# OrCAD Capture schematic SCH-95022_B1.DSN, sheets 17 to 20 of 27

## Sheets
17 Page20 HDMI Display: size C
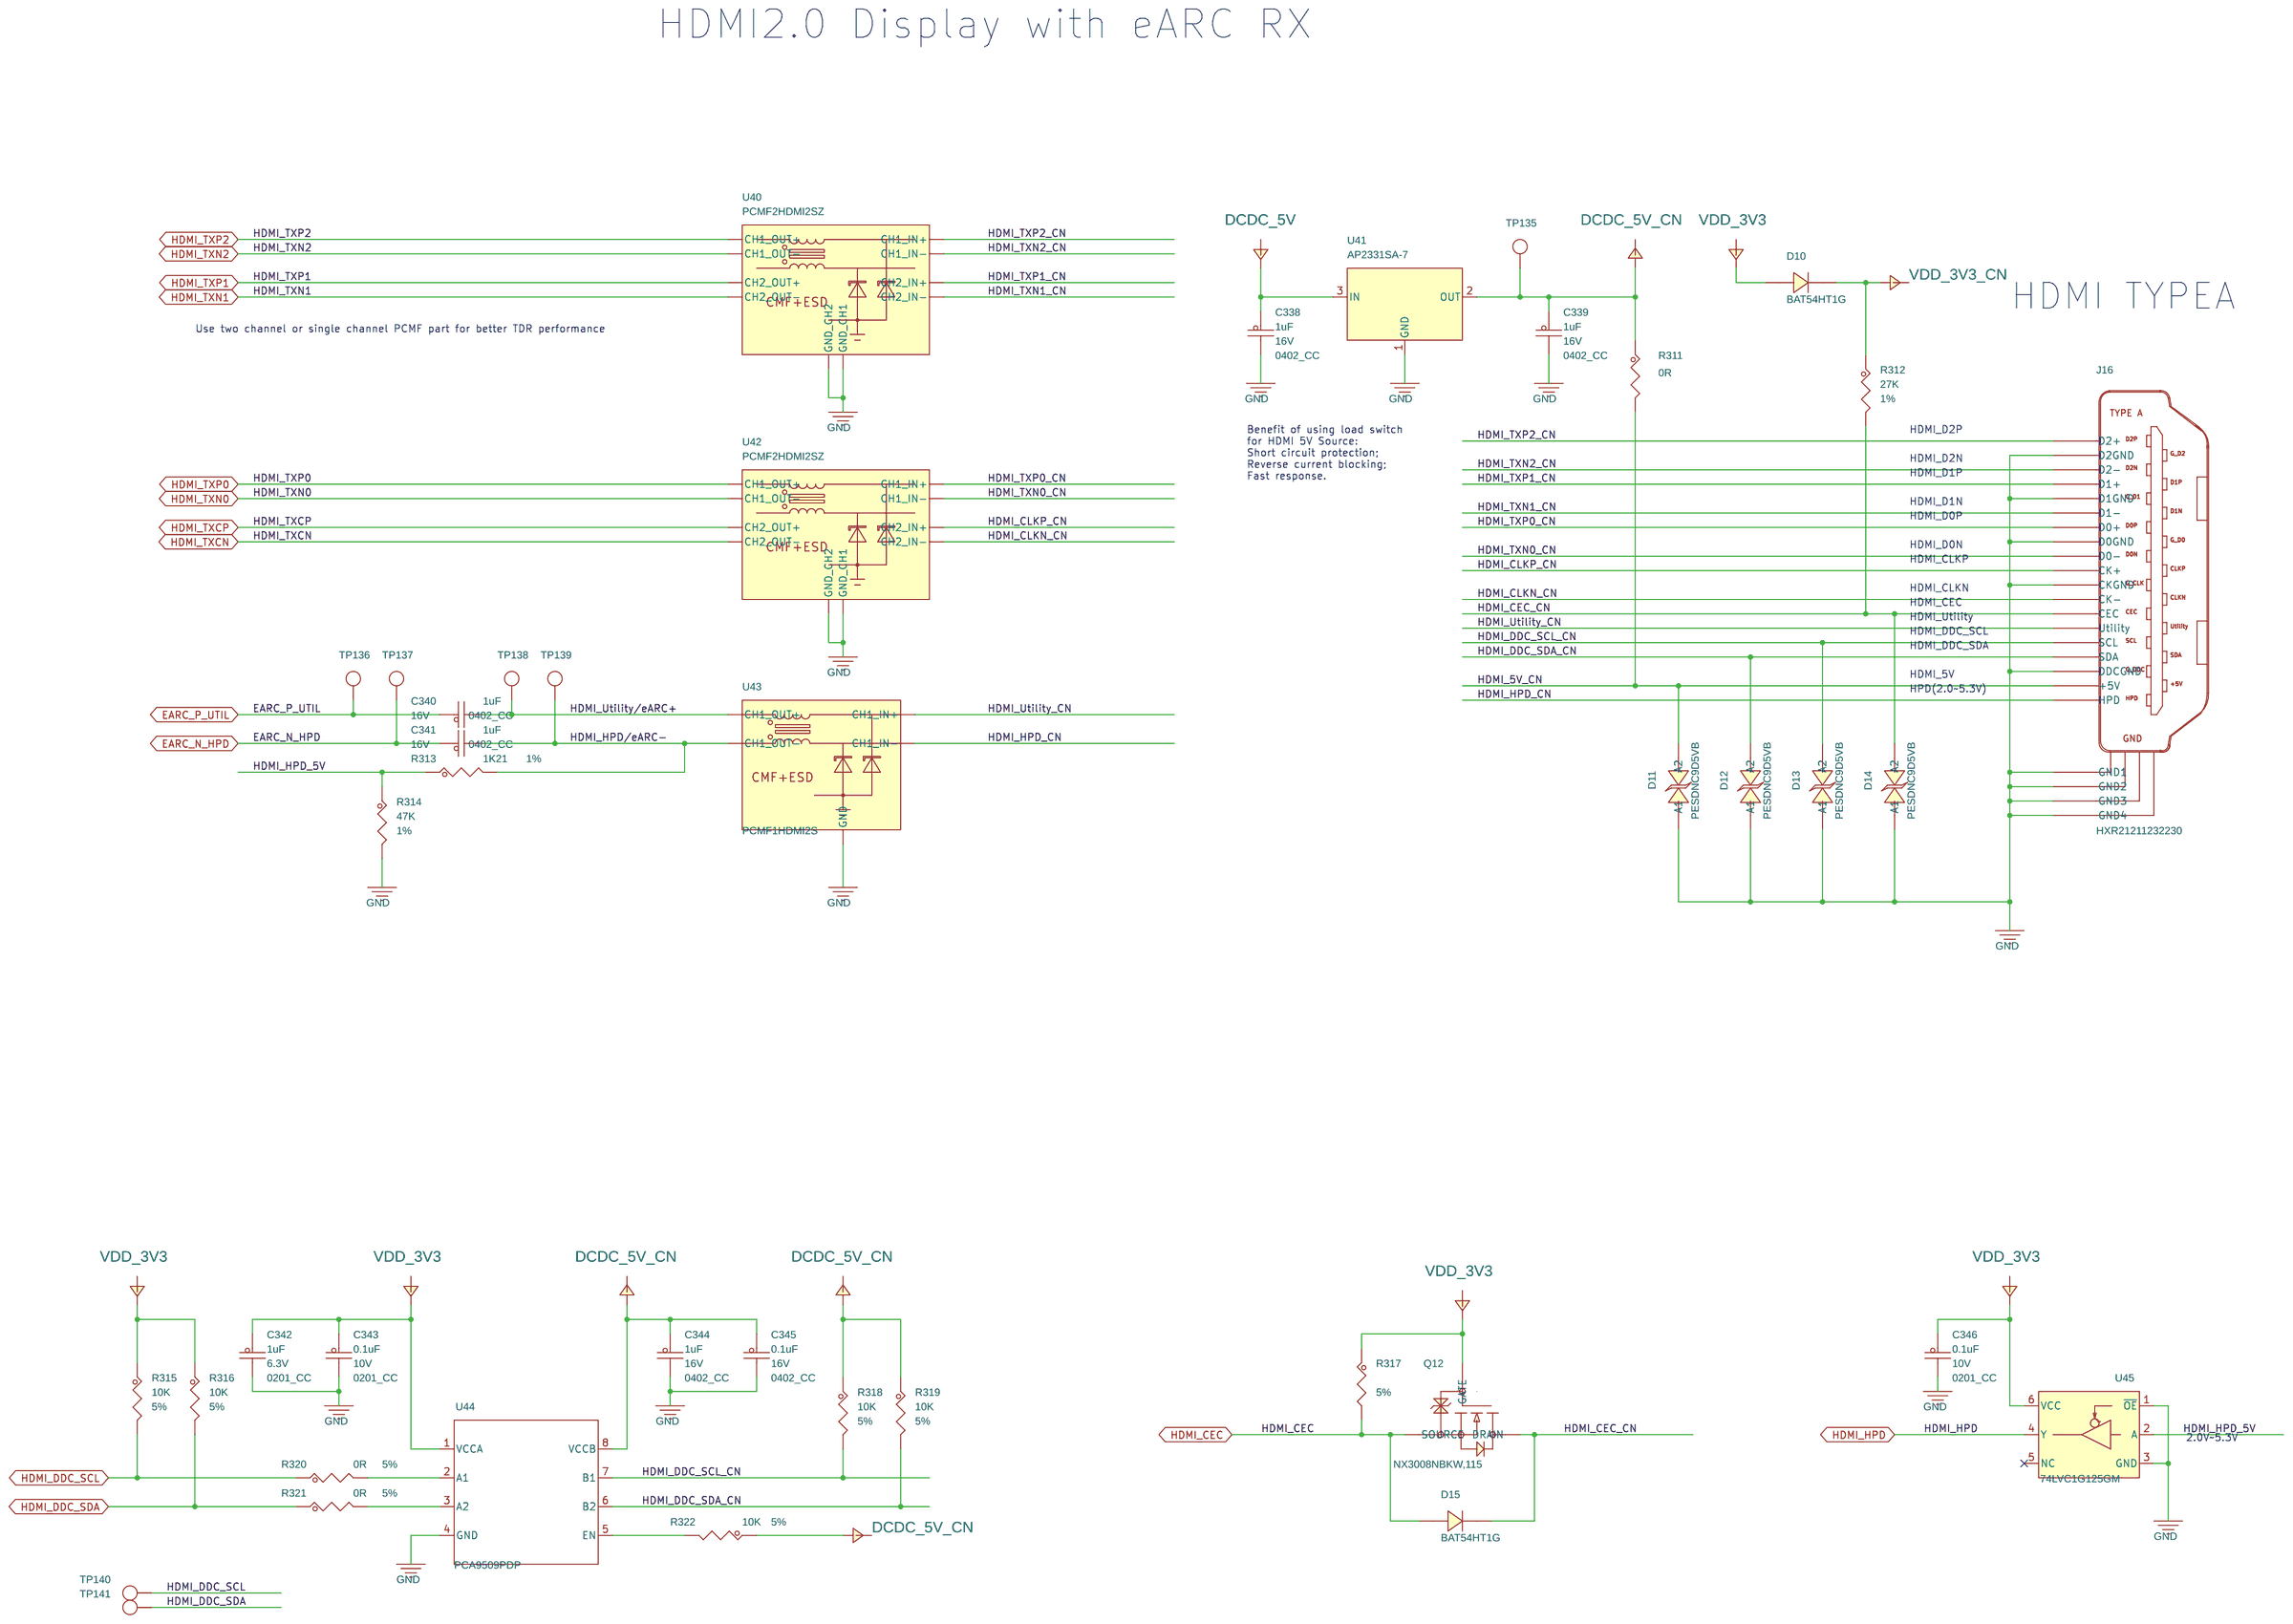
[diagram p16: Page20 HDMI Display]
18 Page23 Audio CODEC: size C
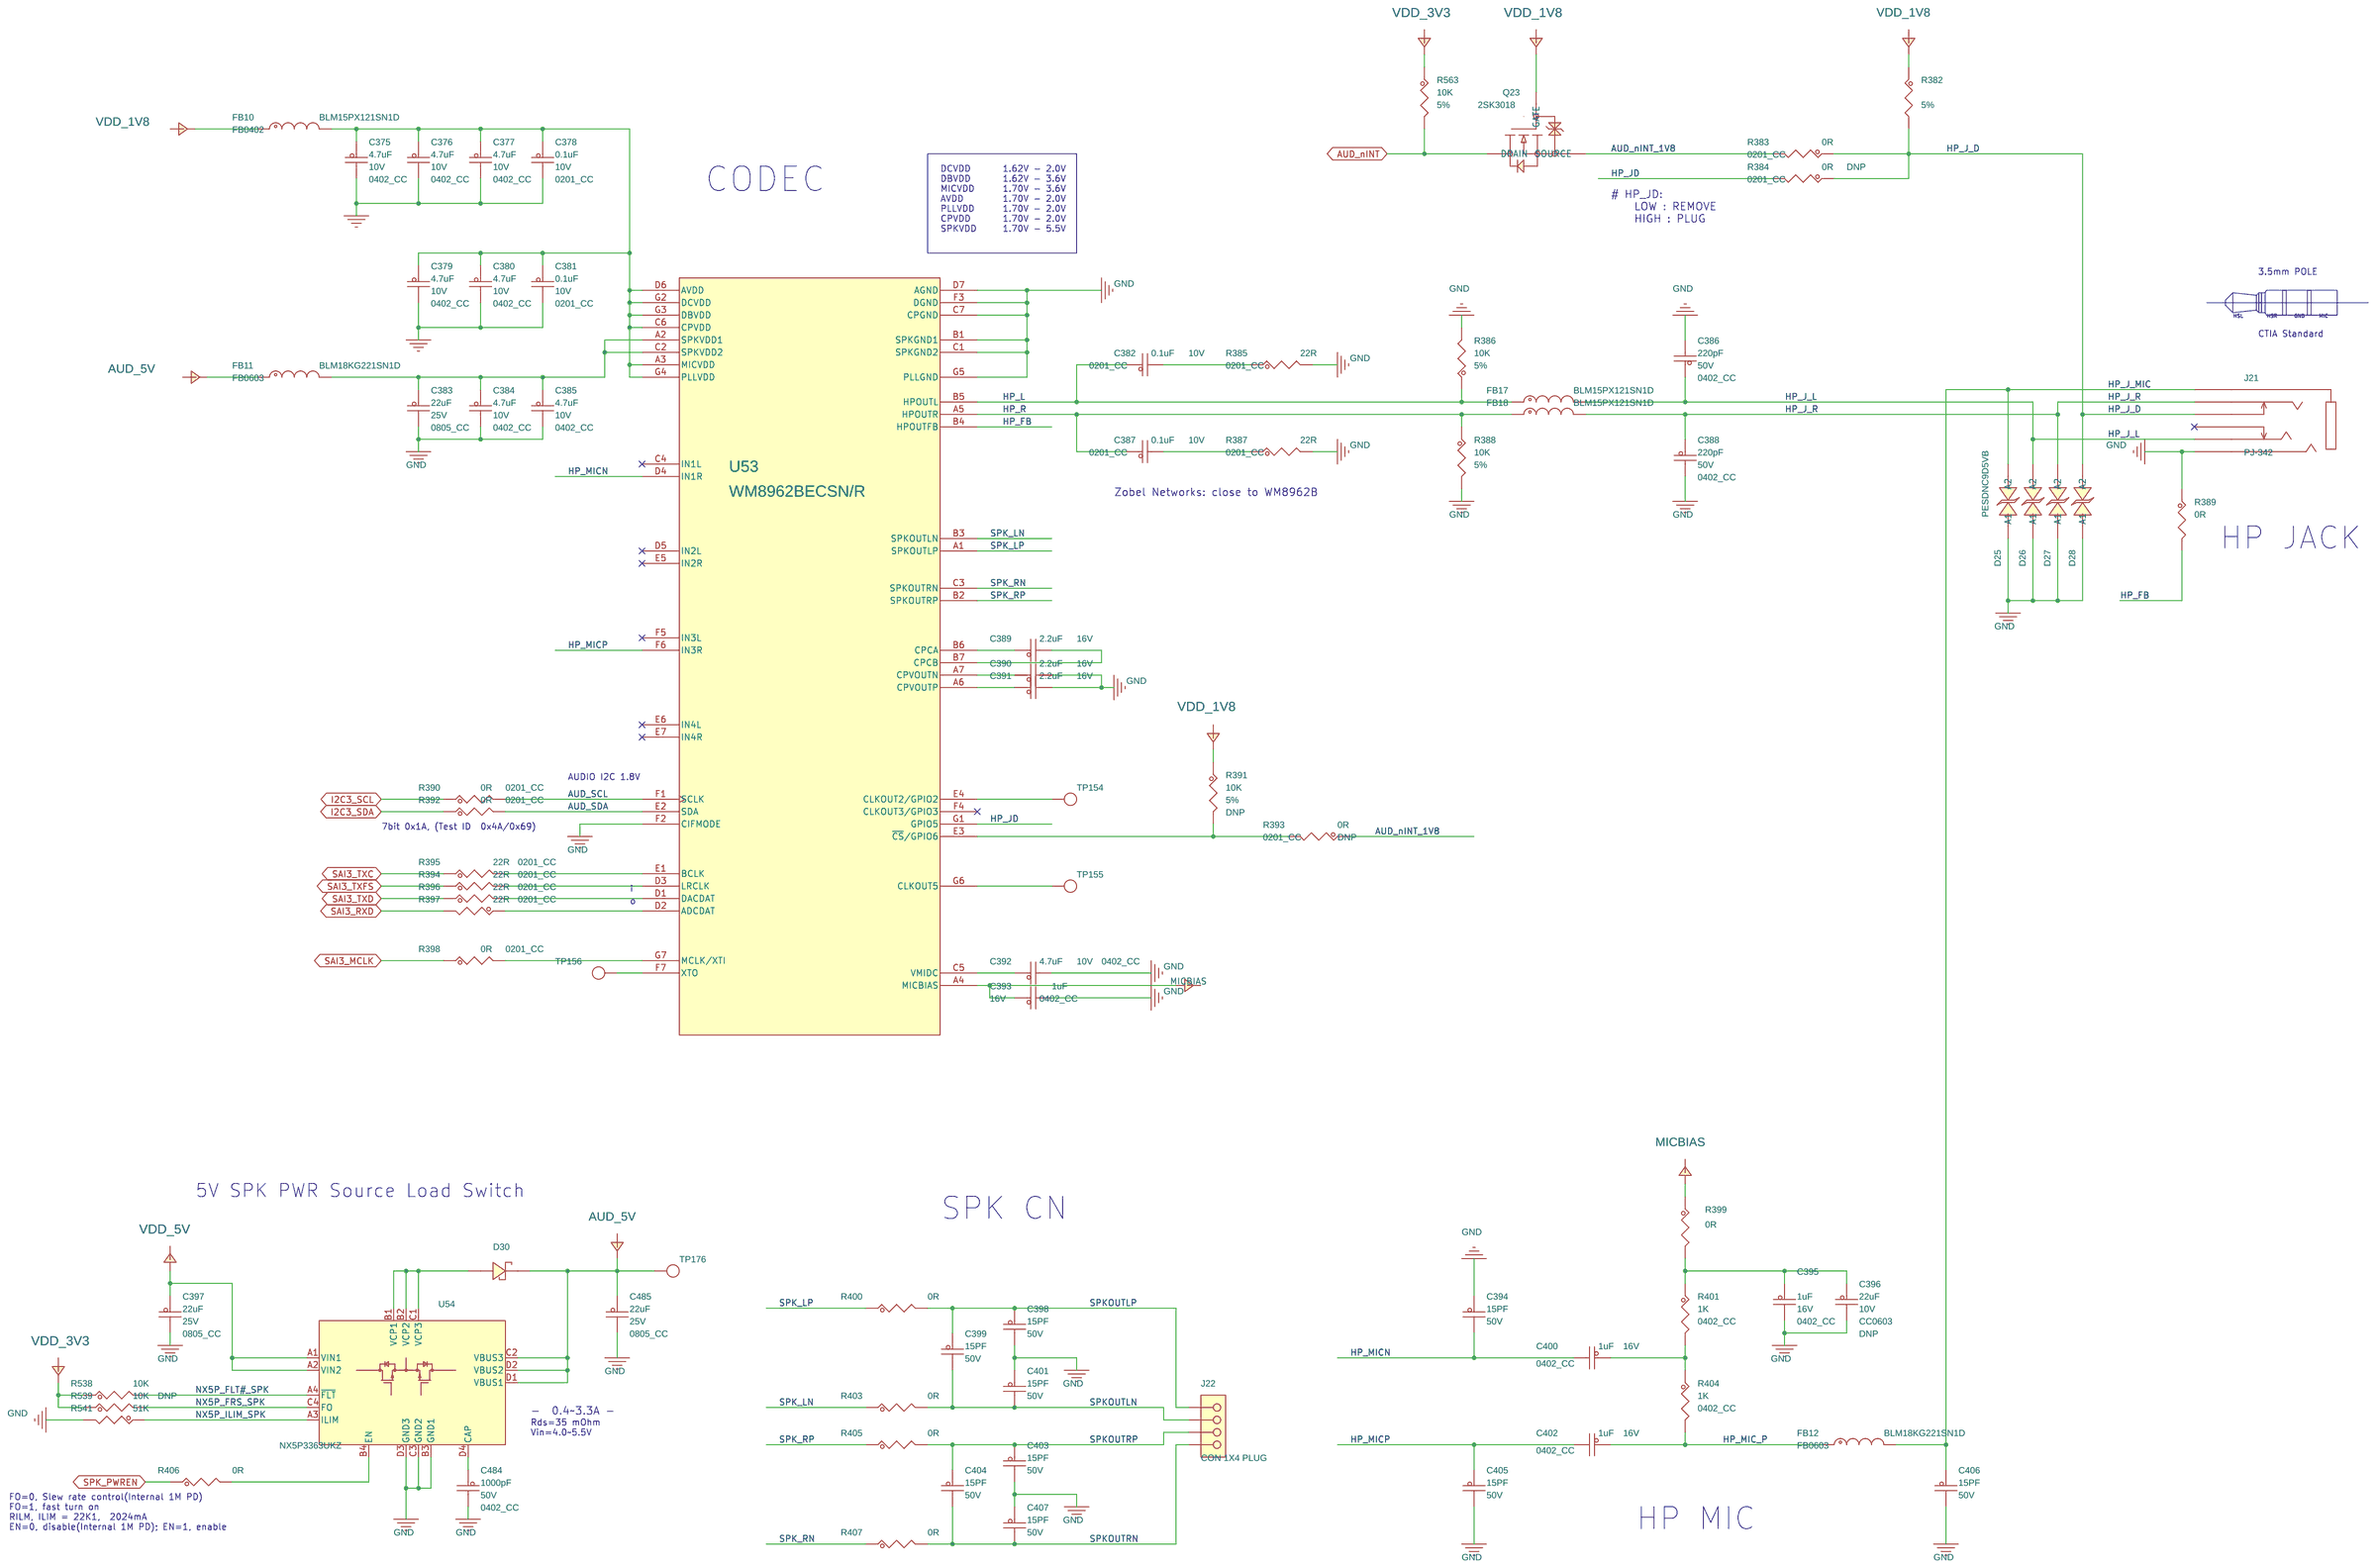
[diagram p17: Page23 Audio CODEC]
19 Page25 M.2 KEY-M PCIe3.0: size A3
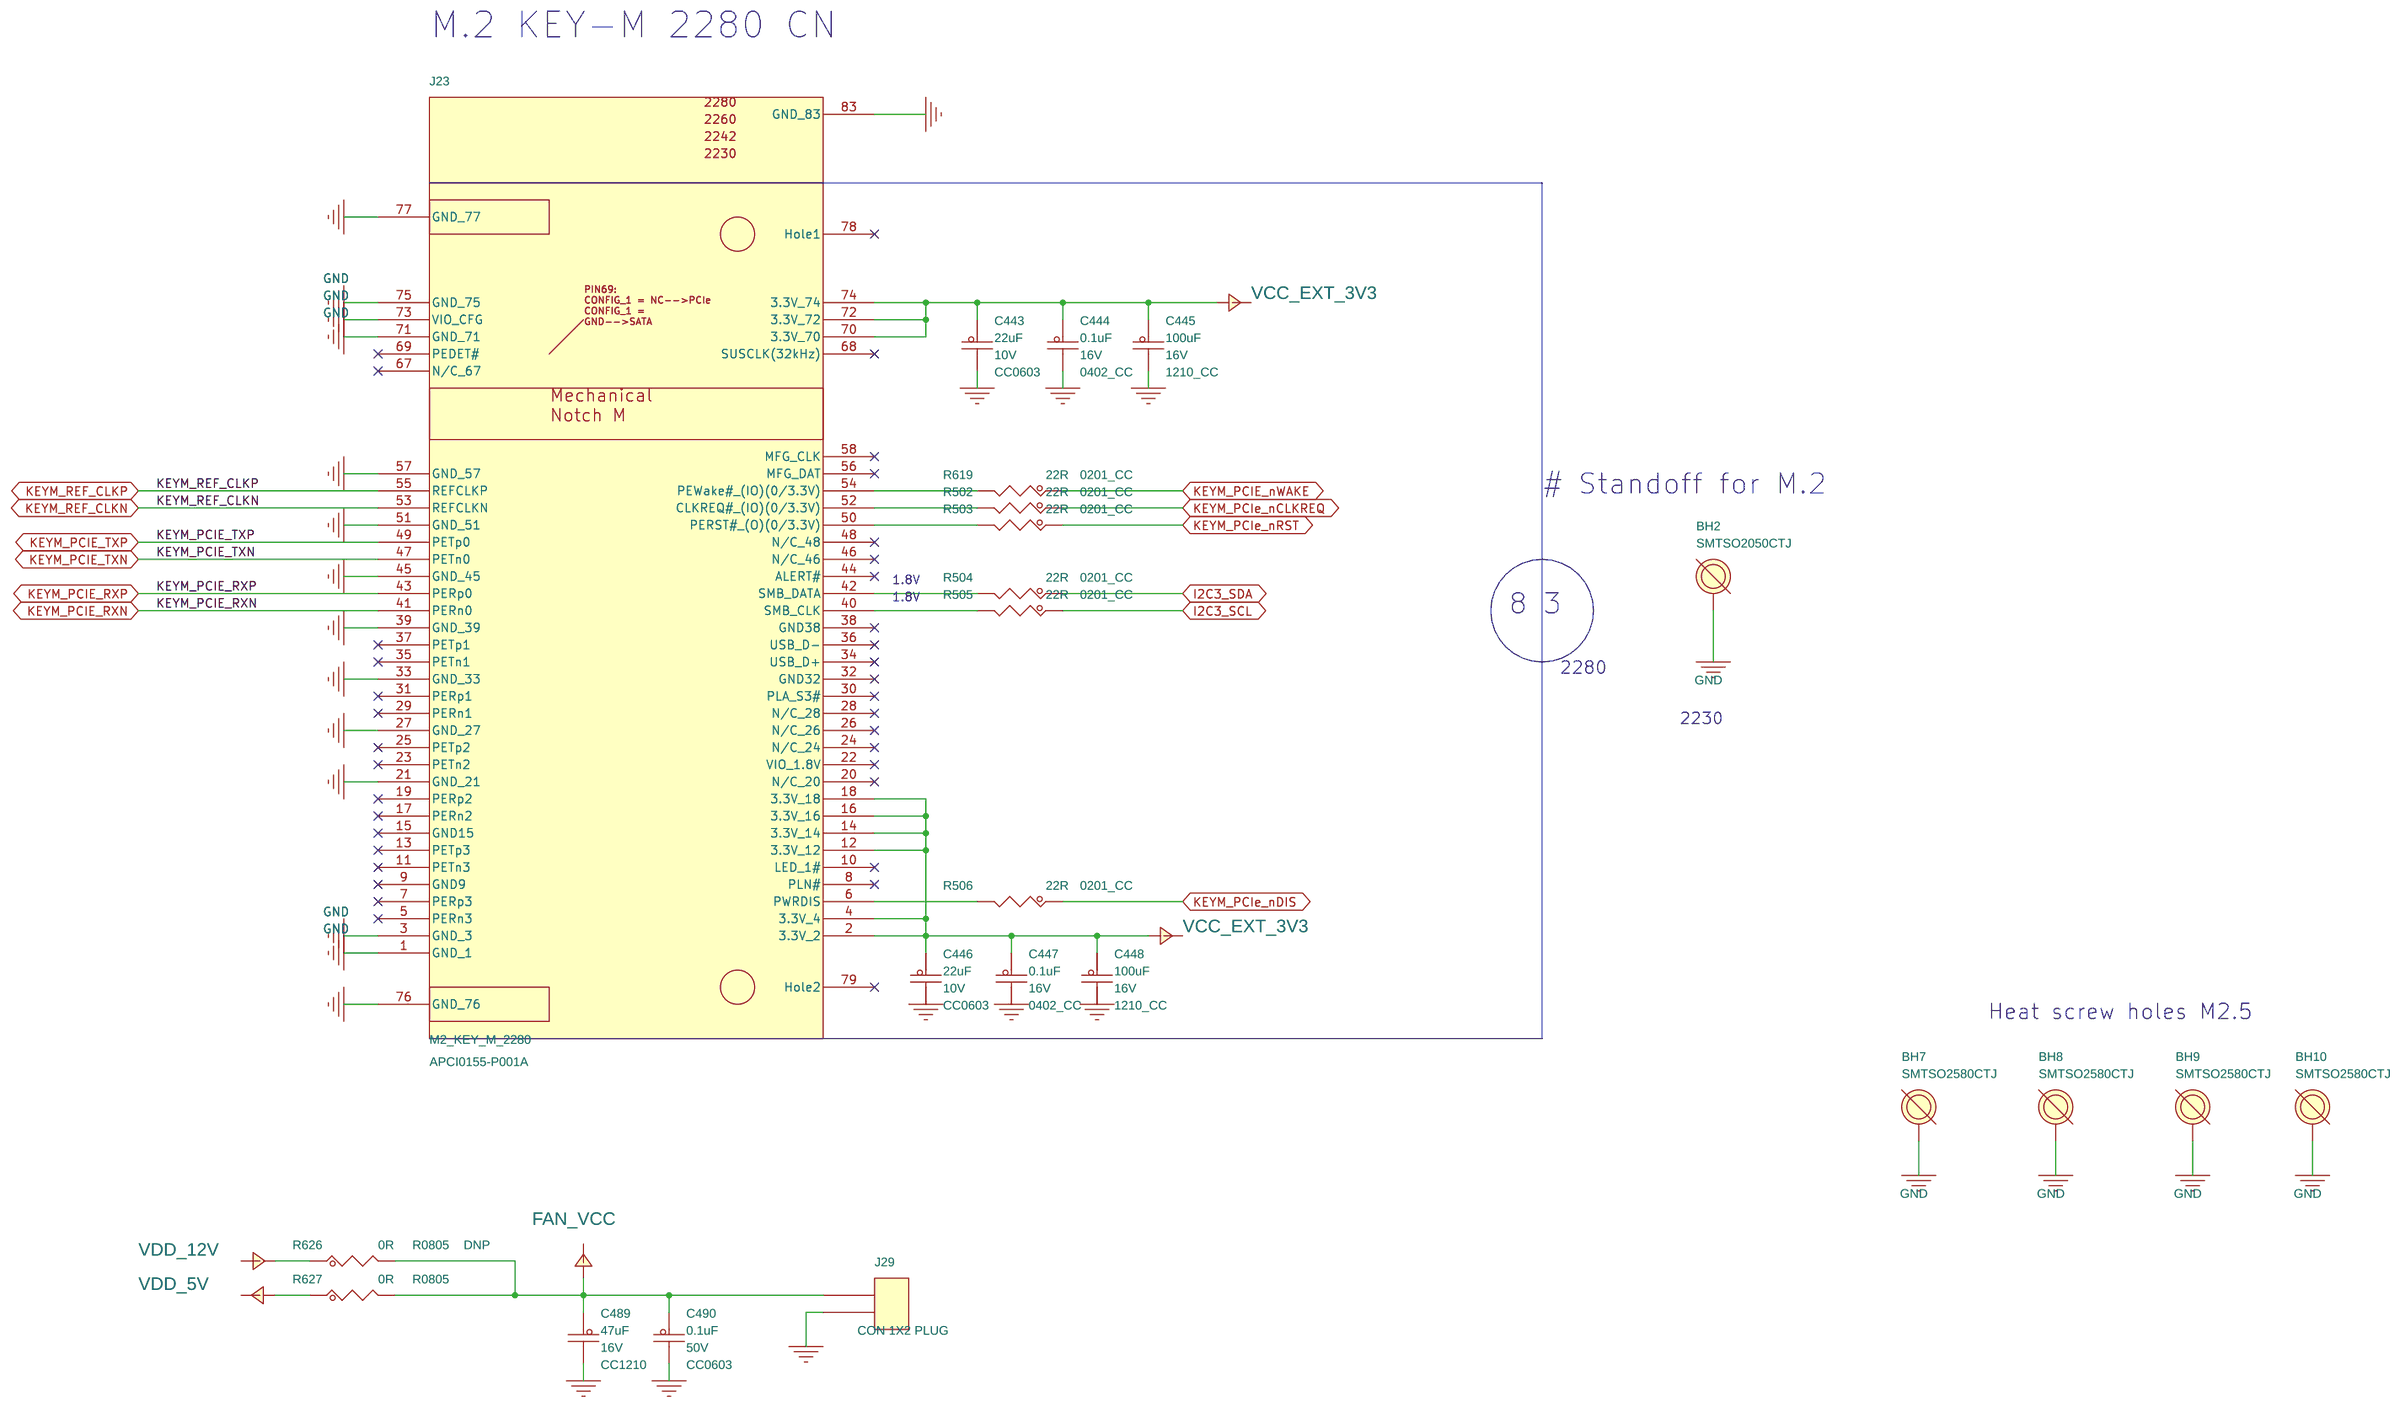
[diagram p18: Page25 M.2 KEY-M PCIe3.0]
20 Page18 LVDS0/1: size C
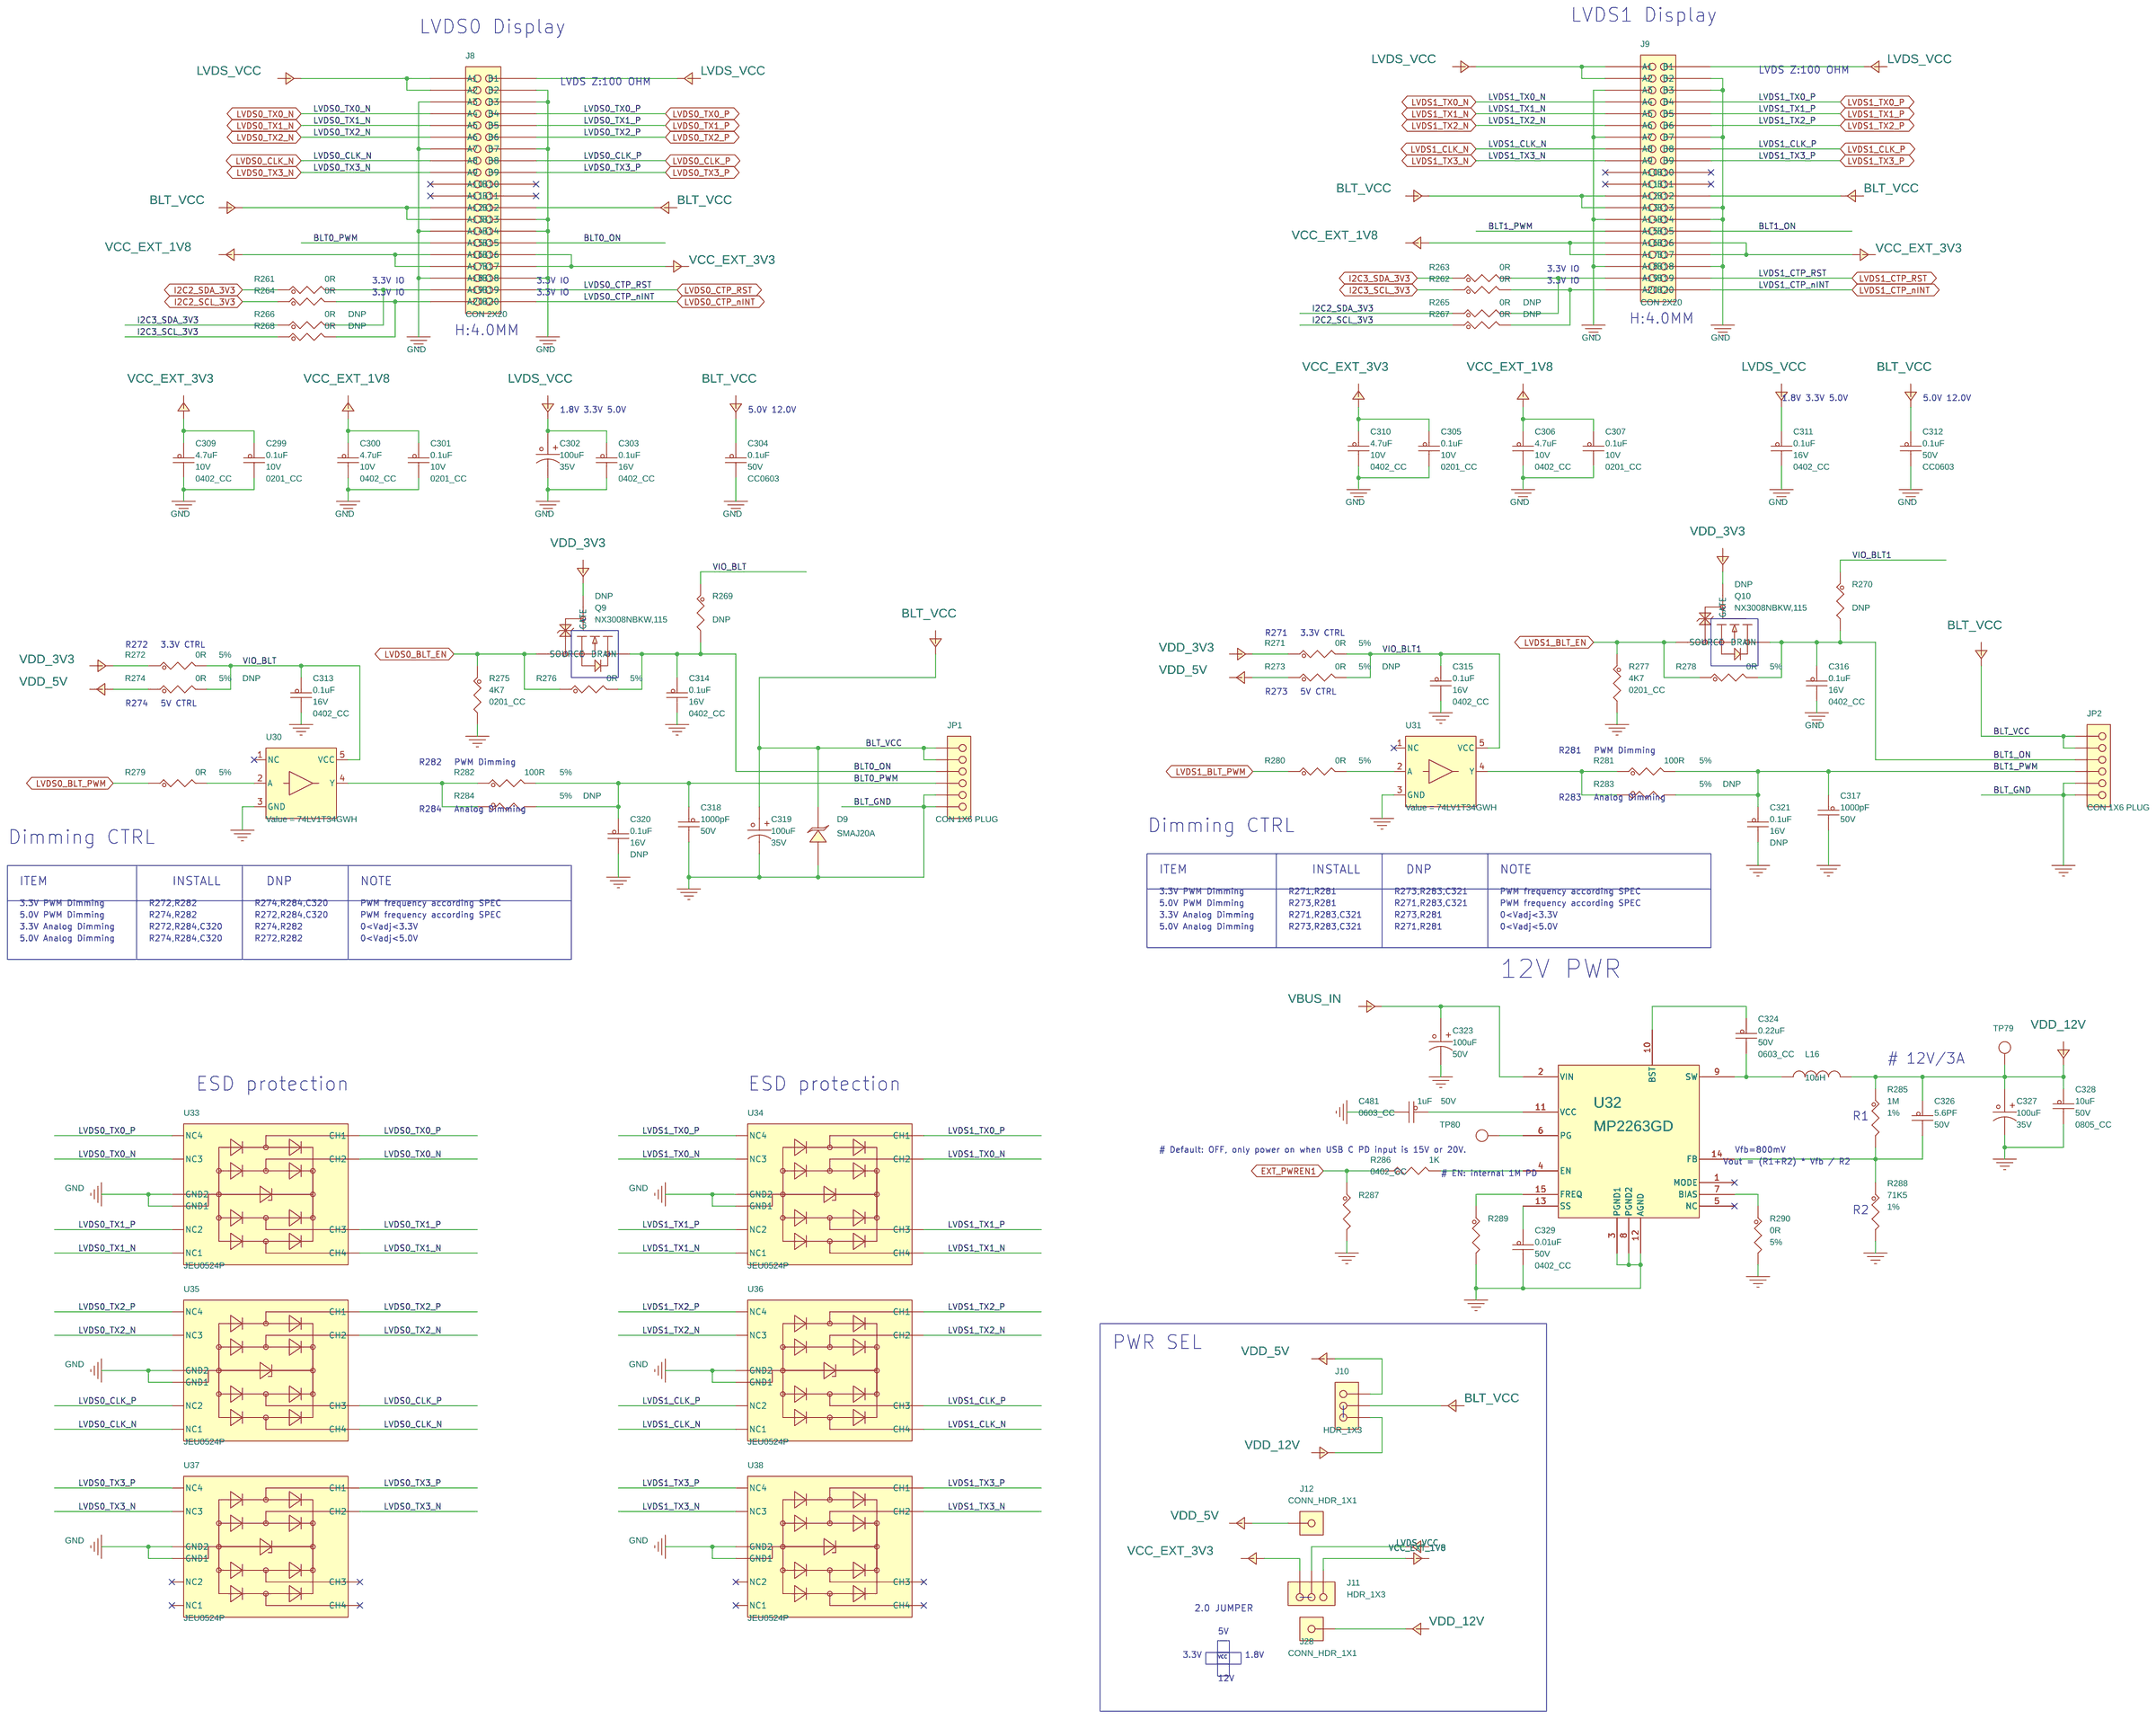
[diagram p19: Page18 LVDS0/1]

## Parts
sheet Page18 LVDS0/1
C299  0.1uF  [0201_CC]
C300  4.7uF  [0402_CC]
C301  0.1uF  [0201_CC]
C302  100uF  [CAP_SMT_6R60X6R60X7R70]
C303  0.1uF  [0402_CC]
C304  0.1uF  [CC0603]
C305  0.1uF  [0201_CC]
C306  4.7uF  [0402_CC]
C307  0.1uF  [0201_CC]
C309  4.7uF  [0402_CC]
C310  4.7uF  [0402_CC]
C311  0.1uF  [0402_CC]
C312  0.1uF  [CC0603]
C313  0.1uF  [0402_CC]
C314  0.1uF  [0402_CC]
C315  0.1uF  [0402_CC]
C316  0.1uF  [0402_CC]
C317  1000pF  [0402_CC]
C318  1000pF  [0402_CC]
C319  100uF  [CAP_SMT_6R60X6R60X7R70]
C320  0.1uF  [0402_CC]
C321  0.1uF  [0402_CC]
C323  100uF  [CAP_SMT_6R60X6R60X7R70]
C324  0.22uF  [0603_CC]
C326  5.6PF  [0402_CC]
C327  100uF  [CAP_SMT_6R60X6R60X7R70]
C328  10uF  [0805_CC]
C329  0.01uF  [0402_CC]
C481  1uF  [0603_CC]
D9  SMAJ20A  [do214ac_ak]
J8  CON 2X20  [con_2x20_2p0_42p3x5p4mm_th]
J9  CON 2X20  [con_2x20_2p0_42p3x5p4mm_th]
J10  HDR_1X3  [hdr103_78mil]
J11  HDR_1X3  [hdr103_78mil]
J12  CONN_HDR_1X1  [hdr101_78mil]
J28  CONN_HDR_1X1  [hdr101_78mil]
JP1  CON 1X6 PLUG  [con_1x6_2_th]
JP2  CON 1X6 PLUG  [con_1x6_2_th]
L16  10uH  [ind2_11p5x10p3_sm]
Q9  NX3008NBKW,115  [sc70_3]
Q10  NX3008NBKW,115  [sc70_3]
R261  0R  [0402_CC]
R262  0R  [0402_CC]
R263  0R  [0402_CC]
R264  0R  [0402_CC]
R265  0R  [0402_CC]
R266  0R  [0402_CC]
R267  0R  [0402_CC]
R268  0R  [0402_CC]
R269  100K  [0402_CC]
R270  100K  [0402_CC]
R271  0R  [0402_CC]
R272  0R  [0402_CC]
R273  0R  [0402_CC]
R274  0R  [0402_CC]
R275  4K7  [0201_CC]
R276  0R  [0402_CC]
R277  4K7  [0201_CC]
R278  0R  [0402_CC]
R279  0R  [0402_CC]
R280  0R  [0402_CC]
R281  100R  [0402_CC]
R282  100R  [0402_CC]
R283  20K  [0402_CC]
R284  20K  [0402_CC]
R285  1M  [0402_CC]
R286  1K  [0402_CC]
R287  100K  [0402_CC]
R288  71K5  [0402_CC]
R289  165K  [0402_CC]
R290  0R  [0402_CC]
TP79  TPAD_050  [TPAD_050]
TP80  TPAD_050  [TPAD_050]
U30  74LV1T34GWH  [sc70-5]
U31  74LV1T34GWH  [sc70-5]
U32  MP2263GD  [dfn15_0p4_2x3]
U33  JEU0524P  [SLP2510P8-10]
U34  JEU0524P  [SLP2510P8-10]
U35  JEU0524P  [SLP2510P8-10]
U36  JEU0524P  [SLP2510P8-10]
U37  JEU0524P  [SLP2510P8-10]
U38  JEU0524P  [SLP2510P8-10]
sheet Page20 HDMI Display
C338  1uF  [0402_CC]
C339  1uF  [0402_CC]
C340  1uF  [0402_CC]
C341  1uF  [0402_CC]
C342  1uF  [0201_CC]
C343  0.1uF  [0201_CC]
C344  1uF  [0402_CC]
C345  0.1uF  [0402_CC]
C346  0.1uF  [0201_CC]
D10  BAT54HT1G  [SOD323]
D11  PESDNC9D5VB  [SOD-923]
D12  PESDNC9D5VB  [SOD-923]
D13  PESDNC9D5VB  [SOD-923]
D14  PESDNC9D5VB  [SOD-923]
D15  BAT54HT1G  [SOD323]
J16  HXR21211232230  [hd-258-00k-10a1]
Q12  NX3008NBKW,115  [sc70_3]
R311  0R  [0402_CC]
R312  27K  [0402_CC]
R313  1K21  [0402_CC]
R314  47K  [0402_CC]
R315  10K  [0402_CC]
R316  10K  [0402_CC]
R317  100K  [0402_CC]
R318  10K  [0402_CC]
R319  10K  [0402_CC]
R320  0R  [0402_CC]
R321  0R  [0402_CC]
R322  10K  [0402_CC]
TP135  TPAD_020  [tpad_020]
TP136  TPAD_020  [tpad_020]
TP137  TPAD_020  [tpad_020]
TP138  TPAD_020  [tpad_020]
TP139  TPAD_020  [tpad_020]
TP140  TPAD_020  [tpad_020]
TP141  TPAD_020  [tpad_020]
U40  PCMF2HDMI2SZ  [wlcsp10_0p4_1p2x1p6mm_smdp]
U41  AP2331SA-7  [SOT-23]
U42  PCMF2HDMI2SZ  [wlcsp10_0p4_1p2x1p6mm_smdp]
U43  PCMF1HDMI2S  [wlcsp5_0p4_0p82x1p22]
U44  PCA9509PDP  [tssop8_a]
U45  74LVC1G125GM  [udfn6_1x1p5mm]
sheet Page23 Audio CODEC
C375  4.7uF  [0402_CC]
C376  4.7uF  [0402_CC]
C377  4.7uF  [0402_CC]
C378  0.1uF  [0201_CC]
C379  4.7uF  [0402_CC]
C380  4.7uF  [0402_CC]
C381  0.1uF  [0201_CC]
C382  0.1uF  [0201_CC]
C383  22uF  [0805_CC]
C384  4.7uF  [0402_CC]
C385  4.7uF  [0402_CC]
C386  220pF  [0402_CC]
C387  0.1uF  [0201_CC]
C388  220pF  [0402_CC]
C389  2.2uF  [0402_CC]
C390  2.2uF  [0402_CC]
C391  2.2uF  [0402_CC]
C392  4.7uF  [0402_CC]
C393  1uF  [0402_CC]
C394  15PF  [0402_CC]
C395  1uF  [0402_CC]
C396  22uF  [CC0603]
C397  22uF  [0805_CC]
C398  15PF  [0402_CC]
C399  15PF  [0402_CC]
C400  1uF  [0402_CC]
C401  15PF  [0402_CC]
C402  1uF  [0402_CC]
C403  15PF  [0402_CC]
C404  15PF  [0402_CC]
C405  15PF  [0402_CC]
C406  15PF  [0402_CC]
C407  15PF  [0402_CC]
C484  1000pF  [0402_CC]
C485  22uF  [0805_CC]
D25  PESDNC9D5VB  [SOD-923]
D26  PESDNC9D5VB  [SOD-923]
D27  PESDNC9D5VB  [SOD-923]
D28  PESDNC9D5VB  [SOD-923]
D30  B5819W  [sod123lf]
FB10  BLM15PX121SN1D  [FB0402]
FB11  BLM18KG221SN1D  [FB0603]
FB12  BLM18KG221SN1D  [FB0603]
FB17  BLM15PX121SN1D  [FB0402]
FB18  BLM15PX121SN1D  [FB0402]
J21  PJ-342  [PJ-342]
J22  CON 1X4 PLUG  [con1x4_2mm_th_303h]
Q23  2SK3018  [SOT_323]
R382  100K  [0402_CC]
R383  0R  [0201_CC]
R384  0R  [0201_CC]
R385  22R  [0201_CC]
R386  10K  [0402_CC]
R387  22R  [0201_CC]
R388  10K  [0402_CC]
R389  0R  [0402_CC]
R390  0R  [0201_CC]
R391  10K  [0402_CC]
R392  0R  [0201_CC]
R393  0R  [0201_CC]
R394  22R  [0201_CC]
R395  22R  [0201_CC]
R396  22R  [0201_CC]
R397  22R  [0201_CC]
R398  0R  [0201_CC]
R399  0R  [0402_CC]
R400  0R  [0402_CC]
R401  1K  [0402_CC]
R403  0R  [0402_CC]
R404  1K  [0402_CC]
R405  0R  [0402_CC]
R406  0R  [0402_CC]
R407  0R  [0402_CC]
R538  10K  [0402_CC]
R539  10K  [0402_CC]
R541  51K  [0402_CC]
R563  10K  [0402_CC]
TP154  TPAD_020  [tpad_020]
TP155  TPAD_020  [tpad_020]
TP156  TPAD_020  [tpad_020]
TP176  TPAD_020  [tpad_020]
U53  WM8962BECSN/R  [BGA49_0P5_3P62X4]
U54  NX5P3363UKZ  [bga16_0p5_2p23x2p23]
sheet Page25 M.2 KEY-M PCIe3.0
BH2  SMTSO2050CTJ  [PTH_3R73x6R20]
BH7  SMTSO2580CTJ  [PTH_4R20x6R20]
BH8  SMTSO2580CTJ  [PTH_4R20x6R20]
BH9  SMTSO2580CTJ  [PTH_4R20x6R20]
BH10  SMTSO2580CTJ  [PTH_4R20x6R20]
C443  22uF  [CC0603]
C444  0.1uF  [0402_CC]
C445  100uF  [1210_CC]
C446  22uF  [CC0603]
C447  0.1uF  [0402_CC]
C448  100uF  [1210_CC]
C489  47uF  [CC1210]
C490  0.1uF  [CC0603]
J23  M2_KEY_M_2280  [M2_KEY_M]
J29  CON 1X2 PLUG  [PHB2X1-2P0-V]
R502  22R  [0201_CC]
R503  22R  [0201_CC]
R504  22R  [0201_CC]
R505  22R  [0201_CC]
R506  22R  [0201_CC]
R619  22R  [0201_CC]
R626  0R  [R0805]
R627  0R  [R0805]

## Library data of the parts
C299 C301 C305 C307 C343 C346 C378 C381 C382 C387 = CAP_NP: CAP CER 0.1uF 10V 20% X5R 0201; CAD_APPROVED: Yes; HEIGHT: 0.35MM; MFG_NAME01: SAMSUNG; MFG_PN01: CL03A104KP3NNNC; Package Size: 0201; Package Type: 7” reel; Polyhex_Number: PD.005.0054; ROHS: Yes; Tolerance: 20%; VOLTAGE: 10V
C300 C306 C309 C310 C375-C377 C379 C380 C384 C385 C392 = CAP_NP: CAP CER 4.7uF 10V 10% X5R 0402; CAD_APPROVED: Yes; HEIGHT: 0.95MM; MFG_NAME01: SAMSUNG; MFG_PN01: CL05A475KP5NRNC; Polyhex_Number: PD.005.0058; ROHS: Yes; Temp Range: -55°C to + 85°C; Tolerance: 10%; VOLTAGE: 10V
C302 C319 C327 = CAP_POL: CAP ALEL 100uF 35V 20% -- SMD; AGILE_PN: 150-79137; CAD_APPROVED: Yes; HEIGHT: 7.7MM; MFG_NAME01: HONORCAP; MFG_PN01: RVT1V101M0607; Polyhex_Number: PD.005.0130; ROHS: Yes; SILK: RVT; Tolerance: 20%; VOLTAGE: 35V
C303 C311 C313-C316 C345 C444 C447 = CAP_NP: CAP CER 0.1UF 16V 10% X5R 0402; CAD_APPROVED: Yes; FPLIST: CC0402_25,CC0402_HD,0402_CC,capc0402_l; HEIGHT: 0.55MM; MFG_NAME01: SAMSUNG; MFG_PN01: CL05B104K05NNNC; Polyhex_Number: PD.005.0036; ROHS: Yes; Tolerance: 10%; VOLTAGE: 16V
C304 C312 C490 = CAP_NP: CAP CER 0.1uF 50V 10% X7R 0603; CAD_APPROVED: Yes; MFG_NAME01: SAMSUNG; MFG_PN01: CL10B104KB8NNNC; Polyhex_Number: PD.005.0061; ROHS: Yes; Tolerance: 10%; VOLTAGE: 50V
C317 C318 C484 = CAP_NP: CAP CER 1000PF 50V 5% C0G 0402; AGILE_PN: 150-76334; CAD_APPROVED: Yes; FPLIST: CC0402_25,CC0402_HD,0402_CC,capc0402_l; HEIGHT: 0.55MM; MFG_NAME01: SAMSUNG; MFG_PN01: CL05B102KB5NNNC; Package Size: 0402; Package Type: 180mm Paper Tape; Polyhex_Number: PD.005.0076; ROHS: Yes; Tolerance: 5%; VOLTAGE: 50V
C320 C321 = CAP_NP: CAP CER 0.1UF 16V 10% X5R 0402; ASSY_OPT: DNP; CAD_APPROVED: Yes; FPLIST: CC0402_25,CC0402_HD,0402_CC,capc0402_l; HEIGHT: 0.55MM; MFG_NAME01: SAMSUNG; MFG_PN01: CL05B104K05NNNC; Polyhex_Number: PD.005.0036; ROHS: Yes; Tolerance: 10%; VOLTAGE: 16V
C323 = CAP_POL: CAP ALEL 100uF 50V 20% -- SMD; AGILE_PN: 150-79137; CAD_APPROVED: Yes; HEIGHT: 7.7MM; MFG_NAME01: HONORCAP; MFG_PN01: VP1H101M0607; Polyhex_Number: PD.005.0134; ROHS: Yes; SILK: RVT; Tolerance: 20%; VOLTAGE: 50V
C324 = CAP_NP: CAP CER 0.22uF 50V 10% X5R 0603; AGILE_PN: 150-79999; CAD_APPROVED: Yes; FPLIST: CC0402_25,CC0402_HD,0402_CC; HEIGHT: 0.55MM; MFG_NAME01: SAMSUNG; MFG_PN01: CL10B224KB8NNNC; Package Size: 0402; Polyhex_Number: PD.005.0118; ROHS: Yes; Temp Range: -55°C to +85°C; Temp_Range: -55°C to +85°C; Tolerance: 10%; VOLTAGE: 50V
C326 = CAP_NP: CAP CER 5.6pF 50V +/-0.5pF C0G 0402; AGILE_PN: 150-75521; CAD_APPROVED: Yes; FPLIST: CC0402_25,CC0402_HD,0402_CC; HEIGHT: 0.55MM; MFG_NAME01: SAMSUNG; MFG_PN01: CL05C5R6DB5NNNC; Package Size: 0402; Package Type: SMD; Polyhex_Number: PD.005.0066; ROHS: Yes; Tolerance: 0.25PF; VOLTAGE: 50V
C328 = CAP_NP: CAP CER 10UF 50V 10% X5R 0805; CAD_APPROVED: Yes; MFG_NAME01: SAMSUNG; MFG_PN01: CL21A106KBYQNNE; Polyhex_Number: PD.005.0060; ROHS: Yes; Tolerance: 10%; VOLTAGE: 50V
C329 = CAP_NP: CAP CER 0.01uF 50V 10% X7R 0402; CAD_APPROVED: Yes; FPLIST: CC0402_25,CC0402_HD,0402_CC,capc0402_l; HEIGHT: 0.55 MM; MFG_NAME01: SAMSUNG; MFG_PN01: CL05B103KB5NNNC; Package Size: 0402; Polyhex_Number: PD.005.0006; ROHS: Yes; Tolerance: 10%; VOLTAGE: 50V
C481 = CAP_NP: CAP CER 1uF 50V 10% X5R 0603; CAD_APPROVED: Yes; FPLIST: CC0603_OV,CC0603,0603_CC; HEIGHT: 0.9MM; MFG_NAME01: SAMSUNG; MFG_PN01: CL10A105KB8NNNC; Package Size: 0603 (1608 Metric); Package Type: Surface Mount, MLCC; Polyhex_Number: PD.005.0063; ROHS: Yes; Rated Voltage: 50V; Temp Range: -55C to +125C; Tolerance: 10%; VOLTAGE: 50V
D9 = DIODE_TVS: DIODE TVS UNI 20V 400W SMA; AGILE_PN: 480-78447; CAD_APPROVED: Yes; HEIGHT: 2.29 MM; MFG_NAME01: LITTELFUSE; Polyhex_Number: PD.020.0075
J8 J9 = CONN_HDR_20X2: CON 2X20 TH 2.0MM CTR 266H AU 116L; AGILE_PN: 210-83074; CAD_APPROVED: Yes; HEIGHT: 6.75 MM; MFG_NAME01: JINRUN; MFG_PN01: AB20046W-R40-01; Package Type: TH; Polyhex_Number: PD.011.0168; ROHS: Yes; Temp Range: -25° C to + 85° C
J10 J11 = CONN_HDR_3X1: PH2.0x2.0 1x3P PA3.9 PC2.8 180; 3D_Mechanical_Footprint_File: ftp://fcl.am.freescale.net/ALLEGRO/step/hdr103_78mil.STEP; CAD_APPROVED: Yes; HEIGHT: 5.9MM; MFG_NAME01: WENZHANGJIMEI; MFG_PN01: P303-11-392028; Polyhex_Number: PD.011.0169; ROHS: Yes
J12 J28 = CONN_HDR_1X1: PH2.0x2.0 1x1P PA3.9 PC2.8 180; HEIGHT: 5.9MM; MFG_NAME01: WENZHANGJIMEI; MFG_PN01: P301-11-392028; Polyhex_Number: PD.011.0170
JP1 JP2 = CONN_HDR_6X1: CON 6PIN HY2.0MM 180 DIP; AGILE_PN: 210-82573; CAD_APPROVED: Yes; HEIGHT: 7.7MM; MFG_NAME01: WENZHANGJIMEI; MFG_PN01: 5001-HY0020C-6P1-00; Polyhex_Number: PD.011.0165; ROHS: Yes; Temp Range: -25°C to + 85°C
L16 = INDUCTOR: IND PWR 10uH@1kHz 7.8A 20% SMT; AGILE_PN: 180-79174; CAD_APPROVED: Yes; HEIGHT: 4MM; MFG_NAME01: SUNLORD; MFG_PN01: MWSA1004S-100MT; Package Size: 10X11MM; Polyhex_Number: PD.012.0062; ROHS: Yes; Temp Range: -55 °C to +125 °C
Q9 Q10 = NX3008NBKW_SOT323: TRAN NMOS SW 30V 350mA AEC-Q101 SC-70; AGILE_PN: 480-79736; ASSY_OPT: DNP; CAD_APPROVED: Yes; HEIGHT: 1.1MM; MFG_NAME01: NEXPERIA; Polyhex_Number: PD.014.0033; ROHS: Yes
R261-R264 R271 R272 R276 R278-R280 R290 R311 R320 R321 R389 R399 R400 R403 R405-R407 = RES: RES MF ZERO OHM 1/16W 5% 0402; AGILE_PN: 470-75394; CAD_APPROVED: Yes; FPLIST: RC0402_25,RC0402_HD,RC0402_X2,0402_CC; HEIGHT: 0.45 MM; MFG_NAME01: YAGEO; MFG_PN01: RC0402JR-070RL; Polyhex_Number: PD.004.0009; ROHS: Yes; Tolerance: 5%; VOLTAGE: 50V
R265-R268 R273 R274 = RES: RES MF ZERO OHM 1/16W 5% 0402; AGILE_PN: 470-75394; ASSY_OPT: DNP; CAD_APPROVED: Yes; FPLIST: RC0402_25,RC0402_HD,RC0402_X2,0402_CC; HEIGHT: 0.45 MM; MFG_NAME01: YAGEO; MFG_PN01: RC0402JR-070RL; Polyhex_Number: PD.004.0009; ROHS: Yes; Tolerance: 5%; VOLTAGE: 50V
R269 R270 = RES: RES MF 100K 1/16W 5% 0402; AGILE_PN: 470-75597; ASSY_OPT: DNP; CAD_APPROVED: Yes; FPLIST: RC0402_25,RC0402_HD,0402_CC; HEIGHT: 0.40 MM; MFG_NAME01: YAGEO; MFG_PN01: RC0402JR-07100KL; Polyhex_Number: PD.004.0004; ROHS: Yes; Temp Range: -55C to +155C; Temp_Range: -55C to +155C; Tolerance: 5%; VOLTAGE: 50V
R275 R277 = RES: RES MF 4K7 1/20W 5% 0201; AGILE_PN: 470-82323; CAD_APPROVED: Yes; FPLIST: RC0201,0201_CC; HEIGHT: 0.26MM; MFG_NAME01: YAGEO; MFG_PN01: RC0201JR-074K7L; Polyhex_Number: PD.004.0072; ROHS: Yes; Temp Range: -55°C ~ 125°C; Temp_Range: -55°C ~ 125°C; Tolerance: 5%; VOLTAGE: 25V
R281 R282 = RES: RES MF 100 OHM 1/16W 5% 0402; AGILE_PN: 470-75394; CAD_APPROVED: Yes; FPLIST: RC0402_25,RC0402_HD,RC0402_X2,0402_CC; HEIGHT: 0.45 MM; MFG_NAME01: YAGEO; MFG_PN01: RC0402JR-07100RL; Polyhex_Number: PD.004.0012; ROHS: Yes; Tolerance: 5%; VOLTAGE: 50V
R283 R284 = RES: RES MF 20K 1/16W 5% 0402; AGILE_PN: 470-75597; ASSY_OPT: DNP; CAD_APPROVED: Yes; FPLIST: RC0402_25,RC0402_HD,0402_CC; HEIGHT: 0.40 MM; MFG_NAME01: YAGEO; MFG_PN01: RC0402JR-0720KL; Polyhex_Number: PD.004.0112; ROHS: Yes; Temp Range: -55C to +155C; Temp_Range: -55C to +155C; Tolerance: 5%; VOLTAGE: 50V
R285 = RES: RES MF 1M 1/16W 1% 0402; AGILE_PN: 470-80575; CAD_APPROVED: Yes; FPLIST: RC0402_25,RC0402_HD,0402_CC; HEIGHT: 0.4MM; MFG_NAME01: YAGEO; MFG_PN01: RC0402FR-071ML; Polyhex_Number: PD.004.0230; ROHS: Yes; Tolerance: 1%
R286 R401 R404 = RES: RES MF 1K 1/16W 5% 0402; CAD_APPROVED: Yes; HEIGHT: 0.4 MM; MFG_NAME01: YAGEO; MFG_PN01: RC0402JR-071KL; Polyhex_Number: PD.004.0007; ROHS: Yes; Tolerance: 5%
R287 R317 R382 = RES: RES MF 100K 1/16W 5% 0402; AGILE_PN: 470-75597; CAD_APPROVED: Yes; FPLIST: RC0402_25,RC0402_HD,0402_CC; HEIGHT: 0.40 MM; MFG_NAME01: YAGEO; MFG_PN01: RC0402JR-07100KL; Polyhex_Number: PD.004.0004; ROHS: Yes; Temp Range: -55C to +155C; Temp_Range: -55C to +155C; Tolerance: 5%; VOLTAGE: 50V
R288 = RES: RES MF 71K5 1/16W 1% 0402; CAD_APPROVED: Yes; FPLIST: RC0402_25,RC0402_HD,0402_CC; HEIGHT: 0.4MM; MFG_NAME01: YAGEO; MFG_PN01: RC0402FR-0771K5L; Polyhex_Number: PD.004.0323; ROHS: Yes; Tolerance: 1%; VOLTAGE: 50V
R289 = RES: RES MF 165K  1/16W 1% 0402; AGILE_PN: 470-31084; CAD_APPROVED: Yes; FPLIST: RC0402_25,RC0402_HD,0402_CC; HEIGHT: 0.40 MM; MFG_NAME01: YAGEO; MFG_PN01: RC0402FR-07165KL; Polyhex_Number: PD.004.0324; ROHS: Yes; Temp Range: -55C to +155C; Temp_Range: -55C to +155C; Tolerance: 1%; VOLTAGE: 50V
TP79 TP80 = TESTLOOP: TEST POINT PAD 50MIL DIA SMT, NO PART TO ORDER; AGILE_PN: 211-76644; ASSY_OPT: DNP; CAD_APPROVED: Yes; HEIGHT: 0.1MM; MFG_NAME01: NOTACOMPONENT; MFG_PN01: NOTACOMPONENT; Polyhex_Number: TEST POINT; ROHS: Yes
U30 U31 = 74LV1T34GWH_TSSOP6: IC BUF NON-INVERT 1.6-5.5V TSSOP5; 3D_Mechanical_Footprint_File: ftp://fcl.am.freescale.net/ALLEGRO/step/sc70-5.STEP; AGILE_PN: 312-83344; CAD_APPROVED: Yes; HEIGHT: 1.1 MM; MFG_NAME01: NEXPERIA; Package Size: TSSOP-5; Polyhex_Number: PD.008.0316; ROHS: Yes; Temp Range: -40  °C - 125 °C
U32 = MP2263GD_DFN15_A: IC VREG SYNC STEP-DOWN DCDC 350KHz-2.5MHz ADJ 3A 3.3-30V DFN15; AGILE_PN: 315-81300; CAD_APPROVED: Yes; HEIGHT: 1.05 MM; MFG_NAME01: MONOLITHIC POWER SYSTEMS; Polyhex_Number: PD.008.0317; ROHS: Yes; Temp Range: -40°C to 125°C; VOLTAGE: 3.3-30V
U33-U38 = TVS_ARRAY: TVS Diode array for ESD Protection 0.65pF; AGILE_PN: 480-79837; CAD_APPROVED: Yes; EN: 301-0-01726; HEIGHT: 0.5MM; MFG_NAME01: Jiejie Microelectronics; Polyhex_Number: PD.020.0022; ROHS: Yes; Temp Range: -55C to +125C; Temp_Range: -55C to +125C
C338-C341 C344 C393 C395 C400 C402 = CAP_NP: CAP CER 1UF 16V 10% X5R 0402; CAD_APPROVED: Yes; FPLIST: CC0402_25,CC0402_HD,0402_CC,capc0402_l; HEIGHT: 0.55MM; MFG_NAME01: SAMSUNG; MFG_PN01: CL05A105KO5NNNC; Polyhex_Number: PD.005.0099; ROHS: Yes; Tolerance: 10%; VOLTAGE: 16V
C342 = CAP_NP: CAP CER 1uF 6.3V 10% X5R 0201; AGILE_PN: 150-79407; CAD_APPROVED: Yes; FPLIST: CC0201,CC0201_HD,0201_CC,0201_CC_012SM_NSP; HEIGHT: 0.35MM; MFG_NAME01: SAMSUNG; MFG_PN01: CL03A105KQ3CSNH; Package Size: 0201; Package Type: 7” reel; Polyhex_Number: PD.005.0030; ROHS: Yes; Tolerance: 10%; VOLTAGE: 6.3V
D10 D15 = DIODE: DIODE SCH 30V 200MA -- SOD323; AGILE_PN: 480-30039; CAD_APPROVED: Yes; HEIGHT: 1.15MM; MFG_NAME01: ON SEMICONDUCTOR; Polyhex_Number: PD.020.0073
D11-D14 D25-D28 = DIODE_TVS_BIDIR: ESD PROTECTOR; CAD_APPROVED: Yes; HEIGHT: 0.7MM; MFG_NAME01: PRISEMI; Polyhex_Number: PD.021.0001; ROHS: Yes
J16 = ATOM010130010052_HDMI_19P: CON 1X19 HDMI SMT 0.5MM 249H AU; CAD_APPROVED: Yes; HEIGHT: 6.33MM; MFG_NAME01: HUAXINR; Package Size: 15X12.05X6.13MM; Package Type: SMT; Polyhex_Number: PD.010.0054; ROHS: Yes; Vendor: HUAXINR
Q12 = NX3008NBKW_SOT323: TRAN NMOS SW 30V 350mA AEC-Q101 SC-70; AGILE_PN: 480-79736; CAD_APPROVED: Yes; HEIGHT: 1.1MM; MFG_NAME01: NEXPERIA; Polyhex_Number: PD.014.0033; ROHS: Yes
R312 = RES: RES MF 27K 1/16W 1% 0402; AGILE_PN: 470-30994; CAD_APPROVED: Yes; FPLIST: RC0402_25,RC0402_HD,0402_CC; HEIGHT: 0.40 MM; MFG_NAME01: YAGEO; MFG_PN01: RC0402FR-0727KL; Polyhex_Number: PD.004.0105; ROHS: Yes; Temp Range: -55C to +155C; Temp_Range: -55C to +155C; Tolerance: 1%; VOLTAGE: 50V
R313 = RES: RES MF 1K21 1/16W 1% 0402; AGILE_PN: 470-76075; CAD_APPROVED: Yes; FPLIST: RC0402_25,RC0402_HD,0402_CC; HEIGHT: 0.4MM; MFG_NAME01: YAGEO; MFG_PN01: RC0402FR-071K21L; Polyhex_Number: PD.004.0278; ROHS: Yes; Tolerance: 1%
R314 = RES: RES MF 47K  1/16W 1% 0402; AGILE_PN: 470-31023; CAD_APPROVED: Yes; FPLIST: RC0402_25,RC0402_HD,0402_CC; HEIGHT: 0.40 MM; MFG_NAME01: YAGEO; MFG_PN01: RC0402FR-0747KL; Polyhex_Number: PD.004.0194; ROHS: Yes; Temp Range: –55 °C to +155 °C; Temp_Range: –55 °C to +155 °C; Tolerance: 1%; VOLTAGE: 50V
R315 R316 R318 R319 R322 R386 R388 R538 R563 = RES: RES MF 10K 1/16W 5% 0402; AGILE_PN: 470-75557; CAD_APPROVED: Yes; FPLIST: RC0402_25,RC0402_HD,0402_CC; HEIGHT: 0.4 MM; MFG_NAME01: YAGEO; MFG_PN01: RC0402JR-0710KL; Polyhex_Number: PD.004.0010; ROHS: Yes; Tolerance: 5%; VOLTAGE: 50V
TP135-TP141 TP154-TP156 TP176 = TESTLOOP: TEST POINT PAD 0.5MM DIA SMT, NO PART TO ORDER; AGILE_PN: 211-77484; ASSY_OPT: DNP; CAD_APPROVED: Yes; HEIGHT: 0.1MM; MFG_NAME01: NOT A COMPONENT; MFG_PN01: NOT A COMPONENT; Polyhex_Number: TEST POINT; ROHS: Yes
U40 U42 = PCMF2USB3S_10P: IC EMI FILTER FOR DIFF CH W/ ESD PROTECTION 5V WLCSP10; AGILE_PN: 315-81309; CAD_APPROVED: Yes; FPLIST: wlcsp10_0p4_1p2x1p6mm_smdp,wlcsp10_0p4_1p22x1p62; HEIGHT: 0.6MM; MFG_NAME01: NEXPERIA; Polyhex_Number: PD.008.0319; ROHS: Yes; Temp Range: -40C to +85C; Temp_Range: -40C to +85C; VOLTAGE: 5V
U41 = AP2331SA: IC SW CURRENT LIMITED FOR USB 0.4A 2.7-5.2V SOT23; AGILE_PN: 315-81584; CAD_APPROVED: Yes; HEIGHT: 1.2 MM; MFG_NAME01: DIODES INC; Polyhex_Number: PD.008.0320; ROHS: Yes; Temp Range: -40°C to +85°C; VOLTAGE: 2.7-5.2V
U43 = PESD1USB30_A: IC EMI FILTER ESD PROTECTION 15kV/LINE WLCSP5; AGILE_PN: 315-82946; CAD_APPROVED: Yes; HEIGHT: 0.6MM; MFG_NAME01: NEXPERIA; Polyhex_Number: PD.008.0321; Temp Range: -40°C to +85°C
U44 = PCA9509ADP: IC I2C BUS/SMBUS REPEATER LVL XLTR 0.8-2.0V/2.3-5.5V TSSOP8; AGILE_PN: 312-82578; CAD_APPROVED: Yes; HEIGHT: 1.1 MM; MFG_NAME01: NXP SEMICONDUCTORS; MFG_PN01: PCA9509PDP,118; Polyhex_Number: PD.008.0322; ROHS: Yes; Temp Range: -40C to +85C; VOLTAGE: 0.8-2.0V/2.3-5.5V
U45 = 74AUP1G125GN_6P: IC BUF DRV 3STATE 1.65V-5.5V XSON6; AGILE_PN: 315-82475; CAD_APPROVED: yes; HEIGHT: 0.5mm; MFG_NAME01: NEXPERIA; Package Size: 1.5x1.05x0.5mm; Polyhex_Number: PD.008.0323; ROHS: YES
C383 C397 C485 = CAP_NP: CAP CER 22uF 25V 20% X5R 0805; CAD_APPROVED: Yes; HEIGHT: 0.95MM; MFG_NAME01: SAMSUNG; MFG_PN01: CL21A226MAQNNNE; Polyhex_Number: PD.005.0098; ROHS: Yes; Temp Range: -55°C to + 85°C; Tolerance: 20%; VOLTAGE: 25V
C386 C388 = CAP_NP: CAP CER 220pF 50V 10% X7R 0402; CAD_APPROVED: Yes; HEIGHT: 0.95MM; MFG_NAME01: SAMSUNG; MFG_PN01: CL05B221KB5NNNC; Polyhex_Number: PD.005.0028; ROHS: Yes; Temp Range: -55°C to + 85°C; Tolerance: 10%; VOLTAGE: 50V
C389-C391 = CAP_NP: CAP CER 2.2uF 10V 10% X5R 0402; CAD_APPROVED: Yes; FPLIST: CC0402_25,CC0402_HD,0402_CC,capc0402_l; HEIGHT: 0.55 MM; MFG_NAME01: SAMSUNG; MFG_PN01: CL05A225KO5NQNC; Package Size: 0402; Polyhex_Number: PD.005.0041; ROHS: Yes; Tolerance: 10%; VOLTAGE: 16V
C394 C398 C399 C401 C403-C407 = CAP_NP: CAP CER 15pF 50V 5% C0G 0402; AGILE_PN: 150-75720; CAD_APPROVED: Yes; FPLIST: CC0402_25,CC0402_HD,0402_CC; HEIGHT: 0.55MM; MFG_NAME01: SAMSUNG; MFG_PN01: CL05C150JB5NNNC; Package Size: 0402; Polyhex_Number: PD.005.0072; ROHS: Yes; Tolerance: 5%; VOLTAGE: 50V
C396 = CAP_NP: CAP CER 22uF 10V 20% X5R 0603; AGILE_PN: 150-79530; ASSY_OPT: DNP; CAD_APPROVED: Yes; FPLIST: CC0603_OV,CC0603,0603_CC; HEIGHT: 1MM; MFG_NAME01: SAMSUNG; MFG_PN01: CL10A226MP8NUNE; Package Size: 0603; Polyhex_Number: PD.005.0003; ROHS: Yes; SIGNAL_MODEL: DEFAULT_CAPACITOR_2.2e+07pF_2_1; Tolerance: 20%; VOLTAGE: 10V; WVDC: 6.3V
D30 = DIODE_SCHTKY: B5819W SCHOTTKY BARRIER DIODE SOD123LF; AGILE_PN: 480-30006; CAD_APPROVED: Yes; EN: 106-2-00107; FPLIST: sod123lf,SOD123; HEIGHT: 1.0 MM; MFG_NAME01: JSCJ-ELEC; Polyhex_Number: PD.020.0003; ROHS: Yes
FB10 FB17 FB18 = Ferrite_Bead: FERRITE 0402 120Ohm@100MHz 2A; HEIGHT: 0.5mm; Irms: <Irms>; MFG_NAME01: Murata; Polyhex_Number: PD.009.0006; Temp Range: -55C to +125C; Temp_Range: -55C to +125C
FB11 FB12 = Ferrite_Bead: FERRITE 0603 220Ohm@100MHz 2A; HEIGHT: 0.5mm; Irms: <Irms>; MFG_NAME01: Murata; Polyhex_Number: PD.009.0001; Temp Range: -55C to +125C; Temp_Range: -55C to +125C
J21 = PJ-31060: 3.5mm PHONE JACK H=4.0MM SMT TYPE CONNECTOR; MFG_NAME01: JINSHUNLAI; Polyhex_Number: PD.010.0048
J22 = CONN_HDR_4X1: CON 4PIN HY2.0MM 180 DIP; 3D_Mechanical_Footprint_File: http://www.hxdy.com/NewProductsLook.asp?id=18; CAD_APPROVED: Yes; HEIGHT: 7.7MM; MFG_NAME01: WENZHANGJIMEI; MFG_PN01: 5001-HY0020C-4P1-00; Polyhex_Number: PD.011.0172; ROHS: Yes; Temp Range: -25 to +85°C
Q23 = 2SK3018_SOT323: NMOS SW 30V 100mA SOT-323; MFG_NAME01: CHANGJING ELECTRONICS; Polyhex_Number: PD.014.0008
R383 R390 R392 R398 = RES: RES MF ZERO OHM 1/20W 5% 0201; AGILE_PN: 470-82323; CAD_APPROVED: Yes; FPLIST: RC0201,0201_CC; HEIGHT: 0.26MM; MFG_NAME01: YAGEO; MFG_PN01: RC0201JR-070RL; Polyhex_Number: PD.004.0171; ROHS: Yes; Temp Range: -55°C ~ 125°C; Temp_Range: -55°C ~ 125°C; Tolerance: 5%; VOLTAGE: 25V
R384 R393 = RES: RES MF ZERO OHM 1/20W 5% 0201; AGILE_PN: 470-82323; ASSY_OPT: DNP; CAD_APPROVED: Yes; FPLIST: RC0201,0201_CC; HEIGHT: 0.26MM; MFG_NAME01: YAGEO; MFG_PN01: RC0201JR-070RL; Polyhex_Number: PD.004.0171; ROHS: Yes; Temp Range: -55°C ~ 125°C; Temp_Range: -55°C ~ 125°C; Tolerance: 5%; VOLTAGE: 25V
R385 R387 R394-R397 R502-R506 R619 = RES: RES MF 22 OHM 1/20W 5% 0201; AGILE_PN: 470-82323; CAD_APPROVED: Yes; FPLIST: RC0201,0201_CC; HEIGHT: 0.26MM; MFG_NAME01: YAGEO; MFG_PN01: RC0201JR-0722RL; Polyhex_Number: PD.004.0173; ROHS: Yes; Temp Range: -55°C ~ 125°C; Temp_Range: -55°C ~ 125°C; Tolerance: 5%; VOLTAGE: 25V
R391 R539 = RES: RES MF 10K 1/16W 5% 0402; AGILE_PN: 470-75557; ASSY_OPT: DNP; CAD_APPROVED: Yes; FPLIST: RC0402_25,RC0402_HD,0402_CC; HEIGHT: 0.4 MM; MFG_NAME01: YAGEO; MFG_PN01: RC0402JR-0710KL; Polyhex_Number: PD.004.0010; ROHS: Yes; Tolerance: 5%; VOLTAGE: 50V
R541 = RES: RES MF 51K 1/16W 5% 0402; CAD_APPROVED: Yes; HEIGHT: 0.23mm; MFG_NAME01: YAGEO; MFG_PN01: RC0402FR-0751KL; Polyhex_Number: PD.004.0184; ROHS: Yes; Tolerance: 5%; VOLTAGE: 50V
U53 = WM8962_BGA_49P_A: IC AUDIO CODEC 24BIT DAC 2 CH ADC 1.8V BGA49; 3D_Mechanical_Footprint_File: ftp://fcl.am.freescale.net/ALLEGRO/step/BGA49_0P5_3P62X4.STEP; AGILE_PN: 315-80353; CAD_APPROVED: Yes; HEIGHT: 0.75MM; MFG_NAME01: WOLFSON MICROELECTRONICS; Polyhex_Number: PD.008.0327; ROHS: Yes; VOLTAGE: 1.8V
U54 = NX5P3290_WLCSP16: IC SW PWR CURRENT LIMITER ADJ 0.4-3.3A 4-5.5V WLCSP16; AGILE_PN: 315-82308; CAD_APPROVED: Yes; HEIGHT: 0.595MM; MFG_NAME01: NXP SEMICONDUCTORS; Polyhex_Number: PD.008.0314; ROHS: Yes; Temp Range: -40°C ~ 85°C; Temp_Range: -40°C ~ 85°C; VOLTAGE: 4-5.5V
BH2 = MOUNT_HOLE: FASTENER STANDOFF M2 Length-5.0mm; AGILE_PN: 280-77165; CAD_APPROVED: Yes; HEIGHT: 5.0MM; MFG_NAME01: SINHOOST; Polyhex_Number: PD.019.0017; ROHS: Yes
BH7-BH10 = MOUNT_HOLE: FASTENER STANDOFF M2.5 Length-8.0mm; AGILE_PN: 280-77165; CAD_APPROVED: Yes; HEIGHT: 8.0MM; MFG_NAME01: SINHOOST; Polyhex_Number: PD.019.0018; ROHS: Yes
C443 C446 = CAP_NP: CAP CER 22uF 10V 20% X5R 0603; AGILE_PN: 150-79530; CAD_APPROVED: Yes; FPLIST: CC0603_OV,CC0603,0603_CC; HEIGHT: 1MM; MFG_NAME01: SAMSUNG; MFG_PN01: CL10A226MP8NUNE; Package Size: 0603; Polyhex_Number: PD.005.0003; ROHS: Yes; SIGNAL_MODEL: DEFAULT_CAPACITOR_2.2e+07pF_2_1; Tolerance: 20%; VOLTAGE: 10V; WVDC: 6.3V
C445 C448 = CAP_NP: CAP CER 100uF 16V 20% X5R 1210; AGILE_PN: 150-79142; CAD_APPROVED: Yes; FPLIST: CC1210,1210_CC; HEIGHT: 2.8MM; MFG_NAME01: TAIYO YUDEN; MFG_PN01: EMK325ABJ107MM-T; Package Size: 1210; Polyhex_Number: PD.005.0132; ROHS: Yes; Tolerance: 20%; VOLTAGE: 16V
C489 = CAP_NP: CAP CER 47UF 16V 10% X5R 1210; CAD_APPROVED: Yes; HEIGHT: 2.7 mm; MFG_NAME01: SAMSUNG; MFG_PN01: CL32A476KOJNNNE; Polyhex_Number: PD.005.0133; ROHS: Yes; Tolerance: 10%; VOLTAGE: 16V
J23 = M2_KEY_M_2280: 0.5MM PITCH M.2 H6.7 KEY M; HEIGHT: 6.7MM; MFG_NAME01: LOTES; MFG_PN01: APCI0155-P001A; Polyhex_Number: PD.010.0161
J29 = CON2: CON 2PIN HY2.0MM 180 DIP; Composition: 立式插件HY系列-单排2P间距2.00; Cost: 0.0842; Function: PHB2X1,2.00mm,2A,125V,with buckle,beige,V-DIP,-25C~+85C; HEIGHT: 7.7MM; MFG_NAME01: WENZHANGJIMEI; MFG_PN01: 5001-HY0020C-2P1-00; Part Type: WXA2005WV02; Polyhex_Number: PD.011.xxxx; Rating: OK; Tolerance: A
R626 = RES: RES MF ZERO OHM 1/8W 1% 0805; AGILE_PN: 470-82323; ASSY_OPT: DNP; CAD_APPROVED: Yes; FPLIST: RC0805,0805_CC; HEIGHT: 0.26MM; MFG_NAME01: YAGEO; MFG_PN01: RC0805FR-070RL; Polyhex_Number: PD.004.0266; ROHS: Yes; Temp Range: -55°C ~ 125°C; Temp_Range: -55°C ~ 125°C; Tolerance: 5%; VOLTAGE: 150V
R627 = RES: RES MF ZERO OHM 1/8W 1% 0805; AGILE_PN: 470-82323; CAD_APPROVED: Yes; FPLIST: RC0805,0805_CC; HEIGHT: 0.26MM; MFG_NAME01: YAGEO; MFG_PN01: RC0805FR-070RL; Polyhex_Number: PD.004.0266; ROHS: Yes; Temp Range: -55°C ~ 125°C; Temp_Range: -55°C ~ 125°C; Tolerance: 5%; VOLTAGE: 150V

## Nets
GND: BH2.1 BH7.1 BH8.1 BH9.1 BH10.1 C299.2 C300.2 C301.2 C302.2 C303.2 C304.2 C305.2 C306.2 C307.2 C309.2 C310.2 C311.2 C312.2 C313.2 C314.2 C315.2 C316.2 C317.2 C318.2 C319.2 C320.2 C321.2 C323.2 C327.2 C328.2 C329.2 C338.2 C339.2 C342.2 C343.2 C344.2 C345.2 C346.2 C375.2 C376.2 C377.2 C378.2 C379.2 C380.2 C381.2 C383.2 C384.2 C385.2 C386.2 C388.2 C390.2 C391.2 C392.2 C393.2 C394.1 C395.2 C396.2 C397.2 C398.2 C401.1 C403.2 C405.2 C406.2 C407.1 C443.2 C444.2 C445.2 C446.2 C447.2 C448.2 C481.2 C484.2 C485.2 C489.2 C490.2 D9.A D11.1(A1) D12.1(A1) D13.1(A1) D14.1(A1) D25.1(A1) D26.1(A1) D27.1(A1) D28.1(A1) J8.4(B2) J8.5(A3) J8.6(B3) J8.13(A7) J8.14(B7) J8.26(B13) J8.27(A14) J8.28(B14) J8.35(A18) J8.36(B18) J9.4(B2) J9.5(A3) J9.6(B3) J9.13(A7) J9.14(B7) J9.26(B13) J9.27(A14) J9.28(B14) J9.35(A18) J9.36(B18) J16.2(D2GND) J16.5(D1GND) J16.8(D0GND) J16.11(CKGND) J16.17(DDCGND) J16.G1(GND1) J16.G2(GND2) J16.G3(GND3) J16.G4(GND4) J21.2 J23.1(GND) J23.3(GND) J23.21(GND) J23.27(GND) J23.33(GND) J23.39(GND) J23.45(GND) J23.51(GND) J23.57(GND) J23.71(GND) J23.73(VIO_CFG) J23.75(GND) J23.76(GND) J23.77(GND) J23.83(GND) J29.2 JP1.5 JP1.6 JP2.5 JP2.6 R275.2 R277.2 R287.2 R288.2 R289.2 R290.2 R314.2 R385.2 R386.2 R387.2 R388.2 R389.1 R541.2 U30.3(GND) U31.3(GND) U32.3(PGND1) U32.8(PGND2) U32.12(AGND) U33.3(GND1) U33.8(GND2) U34.3(GND1) U34.8(GND2) U35.3(GND1) U35.8(GND2) U36.3(GND1) U36.8(GND2) U37.3(GND1) U37.8(GND2) U38.3(GND1) U38.8(GND2) U40.B1(GND_CH1) U40.B2(GND_CH2) U41.1(GND) U42.B1(GND_CH1) U42.B2(GND_CH2) U43.B1(GND) U44.4(GND) U45.1(~{OE}) U45.3(GND) U53.B1(SPKGND1) U53.C1(SPKGND2) U53.C7(CPGND) U53.D7(AGND) U53.F2(CIFMODE) U53.F3(DGND) U53.G5(PLLGND) U54.B3(GND1) U54.C3(GND2) U54.D3(GND3) ; also on sheet 4 5 7 8 9 10 11 12 13 14 15 16 21 22 23 24 25 26 27
VBUS_IN: C323.1 U32.2(VIN) ; also on sheet 11 12 13
VCC_EXT_1V8: C300.1 C301.1 C306.1 C307.1 J8.31(A16) J8.33(A17) J9.31(A16) J9.33(A17) J11.3 ; also on sheet 11 21
VCC_EXT_3V3: C299.1 C305.1 C309.1 C310.1 C443.1 C444.1 C445.1 C446.1 C447.1 C448.1 J8.32(B16) J8.34(B17) J9.32(B16) J9.34(B17) J11.1 J23.2(3.3V) J23.4(3.3V) J23.12(3.3V) J23.14(3.3V) J23.16(3.3V) J23.18(3.3V) J23.70(3.3V) J23.72(3.3V) J23.74(3.3V) ; also on sheet 11 21 23 24 25 27
VDD_1V8: FB10.1 Q23.1(GATE) R382.1 R391.1 ; also on sheet 4 5 6 9 10 12 16 21 22 23 24 25 26 27
VDD_3V3: C342.1 C343.1 C346.1 D10.A Q9.1(GATE) Q10.1(GATE) Q12.1(GATE) R271.1 R272.1 R315.1 R316.1 R317.1 R538.1 R539.1 R563.1 U44.1(VCCA) U45.6(VCC) ; also on sheet 4 10 11 12 13 14 15 16 22 24 26 27
VDD_3V3_CN: D10.C(K) R312.1
VDD_5V: C397.1 J10.1 J12.1 R273.1 R274.1 R627.1 U54.A1(VIN1) U54.A2(VIN2) ; also on sheet 11 12 13 24 27
VDD_12V: C326.1 C327.1 C328.1 J10.3 J28.1 L16.2 R285.1 R626.1 TP79.1(Pin1)
AUD_5V: C485.1 D30.C FB11.1 TP176.1(Pin1) U54.C2(VBUS3) U54.D1(VBUS1) U54.D2(VBUS2)
AUD_nINT: Q23.3(DRAIN) R563.2 ; also on sheet 26
AUD_nINT_1V8: Q23.2(SOURCE) R383.2 R393.1
AUD_SCL: R390.2 U53.F1(SCLK)
AUD_SDA: R392.2 U53.E2(SDA)
BLT0_ON: C314.1 J8.30(B15) JP1.3 Q9.3(DRAIN) R269.2 R276.2
BLT0_PWM: C318.1 C320.1 J8.29(A15) JP1.4 R282.2 R284.2
BLT1_ON: C316.1 J9.30(B15) JP2.3 Q10.3(DRAIN) R270.2 R278.2
BLT1_PWM: C317.1 C321.1 J9.29(A15) JP2.4 R281.2 R283.2
BLT_VCC: C304.1 C312.1 C319.1 D9.C J8.23(A12) J8.24(B12) J8.25(A13) J9.23(A12) J9.24(B12) J9.25(A13) J10.2 JP1.1 JP1.2 JP2.1 JP2.2
DCDC_5V: C338.1 U41.3(IN) ; also on sheet 10 11 13 14
DCDC_5V_CN: C339.1 C344.1 C345.1 R311.1 R318.1 R319.1 R322.1 TP135.1(Pin1) U41.2(OUT) U44.8(VCCB)
EARC_N_HPD: C341.1 TP137.1(Pin1) ; also on sheet 7
EARC_P_UTIL: C340.1 TP136.1(Pin1) ; also on sheet 7
EXT_PWREN1: R286.1 R287.1 ; also on sheet 26
FAN_VCC: C489.1 C490.1 J29.1 R626.2 R627.2
HDMI_5V_CN: D11.2(A2) J16.18(+5V) R311.2
HDMI_CEC: D15.A Q12.2(SOURCE) R317.2 ; also on sheet 7
HDMI_CEC_CN: D14.2(A2) D15.C(K) J16.13(CEC) Q12.3(DRAIN) R312.2
HDMI_CLKN_CN: J16.12(CK-) U42.A4(CH2_IN-)
HDMI_CLKP_CN: J16.10(CK+) U42.A3(CH2_IN+)
HDMI_DDC_SCL: R315.2 R320.1 TP140.1(Pin1) ; also on sheet 7
HDMI_DDC_SCL_CN: D13.2(A2) J16.15(SCL) R318.2 U44.7(B1)
HDMI_DDC_SDA: R316.2 R321.1 TP141.1(Pin1) ; also on sheet 7
HDMI_DDC_SDA_CN: D12.2(A2) J16.16(SDA) R319.2 U44.6(B2)
HDMI_HPD: U45.4(Y) ; also on sheet 7
HDMI_HPD/eARC-: C341.2 R313.2 TP139.1(Pin1) U43.C2(CH1_OUT-)
HDMI_HPD_5V: R313.1 R314.1 U45.2(A)
HDMI_HPD_CN: J16.19(HPD) U43.A2(CH1_IN-)
HDMI_TXCN: U42.C4(CH2_OUT-) ; also on sheet 7
HDMI_TXCP: U42.C3(CH2_OUT+) ; also on sheet 7
HDMI_TXN0: U42.C2(CH1_OUT-) ; also on sheet 7
HDMI_TXN0_CN: J16.9(D0-) U42.A2(CH1_IN-)
HDMI_TXN1: U40.C4(CH2_OUT-) ; also on sheet 7
HDMI_TXN1_CN: J16.6(D1-) U40.A4(CH2_IN-)
HDMI_TXN2: U40.C2(CH1_OUT-) ; also on sheet 7
HDMI_TXN2_CN: J16.3(D2-) U40.A2(CH1_IN-)
HDMI_TXP0: U42.C1(CH1_OUT+) ; also on sheet 7
HDMI_TXP0_CN: J16.7(D0+) U42.A1(CH1_IN+)
HDMI_TXP1: U40.C3(CH2_OUT+) ; also on sheet 7
HDMI_TXP1_CN: J16.4(D1+) U40.A3(CH2_IN+)
HDMI_TXP2: U40.C1(CH1_OUT+) ; also on sheet 7
HDMI_TXP2_CN: J16.1(D2+) U40.A1(CH1_IN+)
HDMI_Utility/eARC+: C340.2 TP138.1(Pin1) U43.C1(CH1_OUT+)
HDMI_Utility_CN: J16.14(Utility) U43.A1(CH1_IN+)
HP_FB: R389.2 U53.B4(HPOUTFB)
HP_J_D: D28.2(A2) J21.5 R382.2 R383.1 R384.1
HP_J_L: C386.1 D26.2(A2) FB17.2 J21.4
HP_J_MIC: C406.1 D25.2(A2) FB12.2 J21.1
HP_J_R: C388.1 D27.2(A2) FB18.2 J21.3
HP_JD: R384.2 U53.G1(GPIO5)
HP_L: C382.1 FB17.1 R386.1 U53.B5(HPOUTL)
HP_MIC_P: C402.1 FB12.1 R404.2
HP_MICN: C394.2 C400.2 U53.D4(IN1R)
HP_MICP: C402.2 C405.1 U53.F6(IN3R)
HP_R: C387.1 FB18.1 R388.1 U53.A5(HPOUTR)
I2C2_SCL_3V3: R264.1 R267.1 ; also on sheet 24 25 26
I2C2_SDA_3V3: R261.1 R265.1 ; also on sheet 24 25 26
I2C3_SCL: R390.1 R505.1 ; also on sheet 6 26
I2C3_SCL_3V3: R262.1 R268.1 ; also on sheet 25 26 27
I2C3_SDA: R392.1 R504.1 ; also on sheet 6 26
I2C3_SDA_3V3: R263.1 R266.1 ; also on sheet 25 26 27
KEYM_PCIe_nCLKREQ: R502.1 ; also on sheet 26
KEYM_PCIe_nDIS: R506.1 ; also on sheet 26
KEYM_PCIe_nRST: R503.1 ; also on sheet 26
KEYM_PCIE_nWAKE: R619.1 ; also on sheet 26
KEYM_PCIE_RXN: J23.41(PERn0) ; also on sheet 26
KEYM_PCIE_RXP: J23.43(PERp0) ; also on sheet 26
KEYM_PCIE_TXN: J23.47(PETn0) ; also on sheet 26
KEYM_PCIE_TXP: J23.49(PETp0) ; also on sheet 26
KEYM_REF_CLKN: J23.53(REFCLKN) ; also on sheet 26
KEYM_REF_CLKP: J23.55(REFCLKP) ; also on sheet 26
LVDS0_BLT_EN: Q9.2(SOURCE) R275.1 R276.1 ; also on sheet 26
LVDS0_BLT_PWM: R279.1 ; also on sheet 6
LVDS0_CLK_N: J8.15(A8) U35.5(CH4) U35.6(NC1) ; also on sheet 7
LVDS0_CLK_P: J8.16(B8) U35.4(CH3) U35.7(NC2) ; also on sheet 7
LVDS0_CTP_nINT: J8.40(B20) ; also on sheet 26
LVDS0_CTP_RST: J8.38(B19) ; also on sheet 26
LVDS0_TX0_N: J8.7(A4) U33.2(CH2) U33.9(NC3) ; also on sheet 7
LVDS0_TX0_P: J8.8(B4) U33.1(CH1) U33.10(NC4) ; also on sheet 7
LVDS0_TX1_N: J8.9(A5) U33.5(CH4) U33.6(NC1) ; also on sheet 7
LVDS0_TX1_P: J8.10(B5) U33.4(CH3) U33.7(NC2) ; also on sheet 7
LVDS0_TX2_N: J8.11(A6) U35.2(CH2) U35.9(NC3) ; also on sheet 7
LVDS0_TX2_P: J8.12(B6) U35.1(CH1) U35.10(NC4) ; also on sheet 7
LVDS0_TX3_N: J8.17(A9) U37.2(CH2) U37.9(NC3) ; also on sheet 7
LVDS0_TX3_P: J8.18(B9) U37.1(CH1) U37.10(NC4) ; also on sheet 7
LVDS1_BLT_EN: Q10.2(SOURCE) R277.1 R278.1 ; also on sheet 26
LVDS1_BLT_PWM: R280.1 ; also on sheet 6
LVDS1_CLK_N: J9.15(A8) U36.5(CH4) U36.6(NC1) ; also on sheet 7
LVDS1_CLK_P: J9.16(B8) U36.4(CH3) U36.7(NC2) ; also on sheet 7
LVDS1_CTP_nINT: J9.40(B20) ; also on sheet 26
LVDS1_CTP_RST: J9.38(B19) ; also on sheet 26
LVDS1_TX0_N: J9.7(A4) U34.2(CH2) U34.9(NC3) ; also on sheet 7
LVDS1_TX0_P: J9.8(B4) U34.1(CH1) U34.10(NC4) ; also on sheet 7
LVDS1_TX1_N: J9.9(A5) U34.5(CH4) U34.6(NC1) ; also on sheet 7
LVDS1_TX1_P: J9.10(B5) U34.4(CH3) U34.7(NC2) ; also on sheet 7
LVDS1_TX2_N: J9.11(A6) U36.2(CH2) U36.9(NC3) ; also on sheet 7
LVDS1_TX2_P: J9.12(B6) U36.1(CH1) U36.10(NC4) ; also on sheet 7
LVDS1_TX3_N: J9.17(A9) U38.2(CH2) U38.9(NC3) ; also on sheet 7
LVDS1_TX3_P: J9.18(B9) U38.1(CH1) U38.10(NC4) ; also on sheet 7
LVDS_VCC: C302.1 C303.1 C311.1 J8.1(A1) J8.2(B1) J8.3(A2) J9.1(A1) J9.2(B1) J9.3(A2) J11.2
MICBIAS: C393.1 R399.1 U53.A4(MICBIAS)
NX5P_FLT#_SPK: R538.2 U54.A4(~{FLT})
NX5P_FRS_SPK: R539.2 U54.C4(FO)
NX5P_ILIM_SPK: R541.1 U54.A3(ILIM)
SAI3_MCLK: R398.1 ; also on sheet 6
SAI3_RXD: R397.2 ; also on sheet 6
SAI3_TXC: R395.1 ; also on sheet 6
SAI3_TXD: R396.1 ; also on sheet 6
SAI3_TXFS: R394.1 ; also on sheet 6
SPK_LN: R403.1 U53.B3(SPKOUTLN)
SPK_LP: R400.1 U53.A1(SPKOUTLP)
SPK_PWREN: R406.1 ; also on sheet 26
SPK_RN: R407.1 U53.C3(SPKOUTRN)
SPK_RP: R405.1 U53.B2(SPKOUTRP)
SPKOUTLN: C399.2 C401.2 J22.2 R403.2
SPKOUTLP: C398.1 C399.1 J22.1 R400.2
SPKOUTRN: C404.2 C407.2 J22.4 R407.2
SPKOUTRP: C403.1 C404.1 J22.3 R405.2
VIO_BLT: C313.1 R269.1 R272.2 R274.2 U30.5(VCC)
VIO_BLT1: C315.1 R270.1 R271.2 R273.2 U31.5(VCC)
N110611108: C382.2 R385.1
N110611160: C375.1 C376.1 C377.1 C378.1 C379.1 C380.1 C381.1 FB10.2 U53.A3(MICVDD) U53.C6(CPVDD) U53.D6(AVDD) U53.G2(DCVDD) U53.G3(DBVDD) U53.G4(PLLVDD)
N110611216: C392.1 U53.C5(VMIDC)
N110611259: C395.1 C396.1 R399.2 R401.1
N110611444: C390.1 U53.A7(CPVOUTN)
N110611446: C391.1 U53.A6(CPVOUTP)
N110611476: C389.1 U53.B6(CPCA)
N110611478: C389.2 U53.B7(CPCB)
N110611705: C383.1 C384.1 C385.1 FB11.2 U53.A2(SPKVDD1) U53.C2(SPKVDD2)
N110611944: TP154.1(Pin1) U53.E4(CLKOUT2/GPIO2)
N110611964: R391.2 R393.2 U53.E3(~{CS}/GPIO6)
N110611987: TP155.1(Pin1) U53.G6(CLKOUT5)
N110612031: R394.2 U53.D3(LRCLK)
N110612051: R398.2 U53.G7(MCLK/XTI)
N110612083: R395.2 U53.E1(BCLK)
N110612097: R396.2 U53.D1(DACDAT)
N110612101: R397.1 U53.D2(ADCDAT)
N110612374: C400.1 R401.2 R404.1
N110615461: R320.2 U44.2(A1)
N110615467: R321.2 U44.3(A2)
N110615696: R322.2 U44.5(EN)
N110624866: J23.42(SMB_DATA) R504.2
N110624890: J23.40(SMB_CLK) R505.2
N110625043: J23.52(CLKREQ#_(IO)(0/3.3V)) R502.2
N110625045: J23.50(PERST#_(O)(0/3.3V)) R503.2
N111058712: C387.2 R387.1
N111081472: J23.6(PWRDIS) R506.2
N111305029: C329.1 U32.13(SS)
N111305057: R290.1 U32.7(BIAS)
N111305149: C324.1 U32.10(BST)
N111305177: C324.2 L16.1 U32.9(SW)
N111305232: C326.2 R285.2 R288.1 U32.14(FB)
N111305340: R286.2 U32.4(EN)
N111305353: TP80.1(Pin1) U32.6(PG)
N111305357: C481.1 U32.11(VCC)
N111305372: R289.1 U32.15(FREQ)
N111331467: J8.39(A20) R264.2 R268.2
N111331468: J8.37(A19) R261.2 R266.2
N111331550: R282.1 R284.1 U30.4(Y)
N111331571: R279.2 U30.2(A)
N111331618: R281.1 R283.1 U31.4(Y)
N111331644: R280.2 U31.2(A)
N111331692: J9.39(A20) R262.2 R267.2
N111331702: J9.37(A19) R263.2 R265.2
N111760408: TP156.1(Pin1) U53.F7(XTO)
N111836459: R406.2 U54.B4(EN)
N111836461: C484.1 U54.D4(CAP)
N111836485: D30.A U54.B1(VCP1) U54.B2(VCP2) U54.C1(VCP3)
N112583752: J23.54(PEWake#_(IO)(0/3.3V)) R619.2

Not connected (* = marked no-connect by the designer): J8 19(A10)* 20(B10)* 21(A11)* 22(B11)*; J9 19(A10)* 20(B10)* 21(A11)* 22(B11)*; J21 6*; J23 5(PERn3)* 7(PERp3)* 8(PLN#)* 9(GND9)* 10(LED_1#)* 11(PETn3)* 13(PETp3)* 15(GND15)* 17(PERn2)* 19(PERp2)* 20(N/C)* 22(VIO_1.8V)* 23(PETn2)* 24(N/C)* 25(PETp2)* 26(N/C)* 28(N/C)* 29(PERn1)* 30(PLA_S3#)* 31(PERp1)* 32(GND32)* 34(USB_D+)* 35(PETn1)* 36(USB_D-)* 37(PETp1)* 38(GND38)* 44(ALERT#)* 46(N/C)* 48(N/C)* 56(MFG_DAT)* 58(MFG_CLK)* 67(N/C)* 68(SUSCLK(32kHz))* 69(PEDET#)* 78(Hole1)* 79(Hole2)*; U30 1(NC)*; U31 1(NC)*; U32 1(MODE)* 5(NC)*; U37 4(CH3)* 5(CH4)* 6(NC1)* 7(NC2)*; U38 4(CH3)* 5(CH4)* 6(NC1)* 7(NC2)*; U45 5(NC)*; U53 C4(IN1L)* D5(IN2L)* E5(IN2R)* E6(IN4L)* E7(IN4R)* F4(CLKOUT3/GPIO3)* F5(IN3L)*

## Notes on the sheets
sheet 17
- HDMI2.0 Display with eARC RX
- HDMI TYPEA
- Use two channel or single channel PCMF part for better TDR performance
- Benefit of using load switch
  for HDMI 5V Source:
  Short circuit protection;
  Reverse current blocking;
  Fast response.
- HDMI_D2P
- HDMI_D2N
- HDMI_D1P
- HDMI_D1N
- HDMI_D0P
- HDMI_D0N
- HDMI_CLKP
- HDMI_CLKN
- HDMI_CEC
- HDMI_Utility
- HDMI_DDC_SCL
- HDMI_DDC_SDA
- HDMI_5V
- HPD(2.0~5.3V)
- 2.0V~5.3V
sheet 18
- CODEC
- DCVDD
  DBVDD
  MICVDD
  AVDD
  PLLVDD
  CPVDD
  SPKVDD
- 1.62V - 2.0V
  1.62V - 3.6V
  1.70V - 3.6V
  1.70V - 2.0V
  1.70V - 2.0V
  1.70V - 2.0V
  1.70V - 5.5V
- # HP_JD:
      LOW : REMOVE
      HIGH : PLUG
- 3.5mm POLE
- HSL
- HSR
- GND
- MIC
- CTIA Standard
- Zobel Networks: close to WM8962B
- HP JACK
- AUDIO I2C 1.8V
- 7bit 0x1A, (Test ID  0x4A/0x69)
- i
- o
- 5V SPK PWR Source Load Switch
- SPK CN
- -  0.4~3.3A -
- Rds=35 mOhm
  Vin=4.0~5.5V
- FO=0, Slew rate control(Internal 1M PD)
  FO=1, fast turn on
  RILM, ILIM = 22K1,  2024mA
  EN=0, disable(Internal 1M PD); EN=1, enable
- HP MIC
sheet 19
- M.2 KEY-M 2280 CN
- # Standoff for M.2
- 1.8V
- 1.8V
- 8 3
- 2280
- 2230
- Heat screw holes M2.5
sheet 20
- LVDS1 Display
- LVDS0 Display
- LVDS Z:100 OHM
- LVDS Z:100 OHM
- 3.3V IO
- 3.3V IO
- 3.3V IO
- 3.3V IO
- 3.3V IO
- 3.3V IO
- H:4.0MM
- H:4.0MM
- 1.8V 3.3V 5.0V
- 5.0V 12.0V
- 1.8V 3.3V 5.0V
- 5.0V 12.0V
- R271
- 3.3V CTRL
- R272
- 3.3V CTRL
- R273
- 5V CTRL
- R274
- 5V CTRL
- R281
- PWM Dimming
- R282
- PWM Dimming
- R283
- Analog Dimming
- R284
- Analog Dimming
- Dimming CTRL
- Dimming CTRL
- ITEM
- INSTALL
- DNP
- NOTE
- ITEM
- INSTALL
- DNP
- NOTE
- 3.3V PWM Dimming
- R272,R282
- R274,R284,C320
- PWM frequency according SPEC
- 3.3V PWM Dimming
- 5.0V PWM Dimming
- R271,R281
- R273,R281
- R271,R283,C321
- R273,R283,C321
- PWM frequency according SPEC
- PWM frequency according SPEC
- 5.0V PWM Dimming
- R274,R282
- R272,R284,C320
- PWM frequency according SPEC
- 3.3V Analog Dimming
- R271,R283,C321
- R273,R281
- 0<Vadj<3.3V
- 3.3V Analog Dimming
- R272,R284,C320
- R274,R282
- 0<Vadj<3.3V
- 5.0V Analog Dimming
- R273,R283,C321
- R271,R281
- 0<Vadj<5.0V
- 5.0V Analog Dimming
- R274,R284,C320
- R272,R282
- 0<Vadj<5.0V
- 12V PWR
- # 12V/3A
- ESD protection
- ESD protection
- R1
- # Default: OFF, only power on when USB C PD input is 15V or 20V.
- Vfb=800mV
- Vout = (R1+R2) * Vfb / R2
- # EN: internal 1M PD
- R2
- PWR SEL
- 2.0 JUMPER
- 5V
- 3.3V
- VCC
- 1.8V
- 12V
